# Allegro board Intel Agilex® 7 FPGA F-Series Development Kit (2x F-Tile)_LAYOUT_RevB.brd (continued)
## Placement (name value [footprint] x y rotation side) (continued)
R6892  10.0K  [0402]  31.93 15.37 180 bottom
R6893  10.0K  [0402]  32.95 15.37 180 bottom
R6894  4.70K  [0402]  39.5 40.78 180 bottom
R6895  10.0K  [0402]  32.39 25.35 270 bottom
R6896  100K  [0402]  195.71 64.47 0 bottom
R6897  1M  [0402]  74.05 98.5 0 bottom
R6898  10.0K  [0402]  72.65 42.12 90 bottom
R6899  0  [0402]  99.7 48.34 180 bottom
R6900  0  [0402]  100.72 48.34 180 bottom
R6903  243K  [0402]  220.23 66.75 90 bottom
R6904  0  [0402]  217.69 68.53 0 bottom
R6905  0, DNI  [0402]  217.69 67.64 0 bottom
R6906  0  [0402]  238.64 38.31 270 top
R6907  0  [0402]  236.48 38.31 270 top
R6908  100, DNI  [0402]  100.61 77.37 240 bottom
R6909  100, DNI  [0402]  75.95 66.53 0 bottom
R6910  100, DNI  [0402]  88.72 38.43 90 bottom
R6911  100, DNI  [0402]  75.83 47.97 180 bottom
R6912  100, DNI  [0402]  118.94 48.76 300 bottom
R6913  100, DNI  [0402]  84.6 54.25 60 bottom
R6914  100, DNI  [0402]  84.59 52.12 300 bottom
R6915  100, DNI  [0402]  84.68 59 240 bottom
R6916  100, DNI  [0402]  84.11 57.77 0 bottom
R6917  100, DNI  [0402]  117.29 70.45 60 bottom
R6918  100, DNI  [0402]  117.83 67 0 bottom
R6919  100, DNI  [0402]  84.19 61.45 0 bottom
R6920  100, DNI  [0402]  84.68 62.68 240 bottom
R6921  49.9, DNI  [0402]  74.37 51.39 270 bottom
R6922  49.9, DNI  [0402]  74.11 50.5 270 bottom
R6923  49.9, DNI  [0402]  86.89 52.58 90 bottom
R6924  49.9, DNI  [0402]  86.1 51.5 90 bottom
R6925  49.9, DNI  [0402]  75.51 59.51 90 bottom
R6926  49.9, DNI  [0402]  75.51 58.63 90 bottom
R6927  49.9, DNI  [0402]  75.51 55.58 90 bottom
R6928  49.9, DNI  [0402]  75.51 56.47 90 bottom
R6929  100, DNI  [0402]  108.55 73.65 240 bottom
R6930  DNI  [0402]  75.51 69.17 90 bottom
R6931  DNI  [0402]  75.51 70.06 90 bottom
R6932  DNI  [0402]  75.06 66.53 0 bottom
R6933  DNI  [0402]  75.51 67.86 90 bottom
R6934  DNI  [0402]  90.49 38.43 270 bottom
R6935  DNI  [0402]  86.94 38.43 90 bottom
R6936  DNI  [0402]  74.49 48.42 90 bottom
R6937  DNI  [0402]  74.49 47.53 90 bottom
R6938  DNI  [0402]  94.24 38.12 180 bottom
R6939  DNI  [0402]  95.13 38.12 180 bottom
R6940  100, DNI  [0402]  59.82 43.26 90 top
R6941  100, DNI  [0402]  63.89 43.26 90 top
R6942  100, DNI  [0402]  65.92 43.26 90 top
R6943  100, DNI  [0402]  67.95 43.26 90 top
R6944  0  [0402]  40.33 27.26 270 bottom
R6945  0  [0402]  42.23 27.26 90 bottom
S1  PB Switch  [WURTH_6X3P5_TACT_SWITCH]  211.85 103.58 90 top
S2  PB Switch  [WURTH_6X3P5_TACT_SWITCH]  216.17 103.58 90 top
S3  PB Switch  [WURTH_6X3P5_TACT_SWITCH]  220.49 103.58 90 top
S4  PB Switch  [WURTH_6X3P5_TACT_SWITCH]  224.81 103.58 90 top
S6  PB Switch  [WURTH_6X3P5_TACT_SWITCH]  229.13 103.58 90 top
ST1  -  [SHORT]  209.72 27 180 bottom
ST2  -  [SHORT]  209.19 23.3 0 bottom
ST7  -  [SHORT]  175.35 55.91 270 bottom
ST8  -  [SHORT]  164.6 42.37 90 bottom
ST9  -  [SHORT]  164.6 56.85 90 bottom
ST10  -  [SHORT]  164.6 71.33 90 bottom
ST11  -  [SHORT]  164.6 85.8 90 bottom
ST14  -  [SHORT]  164.6 27.76 90 bottom
ST20  -  [SHORT]  39.63 75.26 180 bottom
ST30  -  [SHORT]  197.49 56.42 90 bottom
ST31  -  [SHORT]  185.17 32.21 0 bottom
ST32  -  [SHORT]  22.87 64.85 0 bottom
ST33  -  [SHORT]  21.98 64.85 0 bottom
ST34  -  [SHORT]  183.52 89.36 90 bottom
SW1  TDA04H0SB1  [DIPSWITCH_SMT_QUAD]  247.66 36.53 90 top
SW2  CVS-01TB  [DIPSWITCH_SMT_SINGLE]  204.17 104.15 180 top
SW3  TDA04H0SB1  [DIPSWITCH_SMT_QUAD]  247.66 51.77 90 top
SW4  TDA04H0SB1  [DIPSWITCH_SMT_QUAD]  247.66 44.15 90 top
SW5  SW_SLIDE_DPDT  [EG2207]  245.52 98.87 0 top
SW6  CVS-01TB  [DIPSWITCH_SMT_SINGLE]  207.78 104.15 180 top
U2  24AA024-I/SN  [SOIC-8]  38.81 23.73 0 bottom
U3  MT25QU02GCBB8E12-0SIT  [T-PBGA24]  26.3 91.26 0 top
U4  MT25QU02GCBB8E12-0SIT  [T-PBGA24]  33.92 91.26 0 top
U5  10M50DAF256I7G  [MAX10_FBGA-256]  26.68 76.15 270 top
U6  TS3A5018RSVR  [UQFN-16]  26.55 95.84 0 bottom
U7  510CBA50M0000BAG  [SMT_OSC_3P2X5MM_4PIN]  13.6 71.45 0 top
U8  AGILEX_FM86  [FBGA-2340]  100.97 61.93 0 top
U9  MT25QU02GCBB8E12-0SIT  [T-PBGA24]  30.61 51.77 180 bottom
U10  510KBA125M000BAGR  [SMT_OSC_3P2X5MM_4PIN]  72.02 76.53 270 top
U12  SN74AUP1G126DCK  [SC70_TI]  56.71 105.11 90 bottom
U15  MT40A2G8VA  [FBGA-78#2]  126.16 22.56 0 top
U16  MT40A2G8VA  [FBGA-78]  113.96 22.56 0 top
U17  MT40A2G8VA  [FBGA-78]  101.77 22.56 0 top
U18  MT40A2G8VA  [FBGA-78]  89.58 22.56 0 top
U19  MT40A2G8VA  [FBGA-78#3]  77.39 22.56 0 top
U20  TPS2557DRBR  [VSON-9]  39.5 29.82 90 bottom
U21  TPS2557DRBR  [VSON-9]  30.38 43.07 90 bottom
U22  MAX3378E  [TSSOP-14]  34.55 63.2 180 bottom
U23  ZL30733LDG1Q089  [ZL30733]  63.51 49.48 180 top
U24  VCC1-9004-114M285  [SMT_OSC_7X5MM_4PIN]  55.63 59.26 180 top
U25  Si52204-A01BGM  [QFN32L]  7.88 47.96 90 bottom
U26  Si53254A-D02AM  [SI53254_QFN40]  21.98 27.13 0 bottom
U27  Si53254A-D02AM  [SI53254_QFN40]  19.82 47.96 270 bottom
U28  SN74LVC2G17DCKR  [SC70-6]  56.14 13.29 0 bottom
U31  SN74LVC2G17DCKR  [SC70-6]  49.16 13.29 0 bottom
U33  TXS0108EPWR  [20-TSSOP]  164.65 100.71 0 bottom
U36  PCA9306DC1/DG,125  [VSSOP8]  194.19 63.07 180 top
U38  PCA9306DC1/DG,125  [VSSOP8]  69.73 97.23 270 bottom
U39  PCA9306DC1/DG,125  [VSSOP8]  69.72 104.59 90 bottom
U44  M24128-BWMN6TP  [SO8]  222.87 58.68 0 top
U45  W25Q64JVSSIM  [WSOIC-8]  33.92 87.45 90 bottom
U46  M24128-BWMN6TP  [SO8]  30.26 30.15 270 bottom
U47  MAX811  [SOT-143]  9.53 98.25 180 top
U48  TPD2EUSB30  [DRT]  5.98 96.06 90 top
U49  CY7C68013A_QFN  [QFN56]  17.1 93.04 0 top
U50  MAX16545BGPF+T / MAX16550AGPN+T  [QFN-22]  226.19 43.89 270 top
U51  FDMC2514SDC  [FDMC8878_VER2]  216.67 52.15 270 bottom
U52  LTC4357  [DFN6_EPAD]  208.67 52.15 180 bottom
U53  LTC4359  [MSOP-8]  216.45 79.81 90 top
U54  MAX16545BGPF+T / MAX16550AGPN+T  [QFN-22]  228.35 80.47 90 top
U56  ISL80101  [DFN-11]  31.25 100.66 90 top
U57  ISL80101  [DFN-11]  35.57 102.19 90 bottom
U58  ISL80101  [DFN-11]  14.74 63.83 270 bottom
U60  LTC1981ES5  [LTC1981ES5_SOT23]  23.63 107.9 270 bottom
U61  LTC3888  [LTC-UHG-52-1550]  179.71 53.16 90 top
U62  LTC7051IV#PBF  [LTC-LQFN-42-1571]  156.47 40.85 0 top
U63  LTC7051IV#PBF  [LTC-LQFN-42-1571]  156.47 55.32 0 top
U64  LTC7051IV#PBF  [LTC-LQFN-42-1571]  156.47 69.8 0 top
U65  LTC7051IV#PBF  [LTC-LQFN-42-1571]  156.47 84.28 0 top
U66  LTC7051IV#PBF  [LTC-LQFN-42-1571]  156.47 26.24 0 top
U70  ISL80101  [DFN-11]  209.3 36.53 270 top
U74  ISL80101  [DFN-11]  199.52 36.53 270 top
U75  ISL80101  [DFN-11]  191.02 92.28 270 top
U76  ISL80101  [DFN-11]  144.28 19.51 0 top
U77  TPS51200DRCR  [VSON-11]  190.89 101.17 180 top
U78  TPS51200DRCR  [VSON-11]  64.65 18.11 90 top
U80  ISL80101  [DFN-11]  64.14 69.67 180 top
U81  ISL80101  [DFN-11]  64.14 61.8 180 top
U87  NLSX4014MUTAG  [UQFN12]  219.34 100.15 0 bottom
U88  NLSX4014MUTAG  [UQFN12]  211.84 100.15 0 bottom
U89  NLSX4014MUTAG  [UQFN12]  8.39 24.34 180 bottom
U90  NLSX4014MUTAG  [UQFN12]  8.39 30.56 180 bottom
U91  SN74AUP1G126DCK  [SC70_TI]  56.71 97.11 90 bottom
U93  LTC7132IY#PBF  [BGA-140#2]  50.3 86.31 0 top
U94  LTM4625IY#PBF  [BGA-25]  196.22 55.32 0 top
U95  LTM4620AIY#PBF  [BGA-144_REVERSE]  181.49 31.96 180 top
U96  LTC7132IY#PBF  [BGA-140]  194.06 77.8 270 top
U97  PCA9534PW,118  [TSSOP16]  30.36 20.65 180 bottom
X1  OCXO - ROM7050PA, DNI  [ROM7050PA]  72.91 41.99 90 top
X2  TX-801, DNI  [TX801_G320]  73.39 42.62 90 top
Y1  25.00MHz  [XTAL_FA-128]  9.28 41.23 0 bottom
Y2  24.00MHz  [XTAL_FA-128]  9.35 94.79 90 top

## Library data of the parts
B1 = Molex_QSFPDD_Cage
B2 = Molex_zQSFP_Cage_0
BT1 = Battery_0
C1 C2 C6-C15 C18 C20 C24 C26 C31-C36 C38-C47 C340-C343 C347-C350 = CAP: signal model: CAP_0201_0.22UF_0.22uF
C16 C17 C19 C21-C23 C25 C27-C30 C37 C48-C101 C107-C111 C122 C133 C135 C137 C139 C141 C143 C145 C150-C153 C157 C159 C162 C167 C169 C171 C173 C175 C177 C179 C184 C185 C187 C189 C191 C194 C195 C197-C200 C202 C203 C205-C221 C224-C246 C248 C249 C251-C267 C270-C291 C293 C295 C297-C302 C305-C307 C309 C310 C313 C314 C317 C318 C323-C325 C327 C328 C331 C332 C335 C336 C344-C346 C351-C386 C394 C395 C397-C418 C420-C424 C432-C436 C444 C449 C451 C456 C460 C461 C466 C467 C470-C473 C482 C483 C485-C494 C496-C509 C514-C517 C522-C524 C533-C541 C545 C546 C548 C549 C572-C591 C598-C606 C609 C620-C629 C651 C655 C659 C663-C665 C691 C694 C696-C698 C701 C702 C711 C719 C723 C729 C737 C738 C747 C755 C756 C765 C773 C775 C783 C791 C865 C869 C920 C925 C928 C929 C936-C938 C945 C958 C961-C963 C966-C975 C977 C981 C983 C987-C1003 C1018-C1026 C1031-C1037 C1042 C1043 C1045 C1046 C1049-C1071 C1073-C1081 C1093 C1098 C1120 C1121 C1123 C1126 C1127 C1149 C1157 C1158 C1164 C1165 C1178-C1180 C1191 C1193 C1194 C1197 C1200 C1201 C1203 C1205 C1206 C1209-C1215 C1218 C1219 C1225-C1237 C1260-C1289 = CAP: User Part Number: PART#; Tolerance: TOL
C112-C115 C525 C530 C542-C544 C550-C552 C561 C562 C571 C1047 C1048 C1072 C1224 = CAP
C116-C121 C123-C128 C144 C146 C147 C160 C178 C180 C181 C192 C201 C204 C222 C223 C247 C250 C268 C269 C292 C296 C304 C308 C311 C312 C315 C316 C319-C322 C326 C329 C330 C333 C334 C337-C339 C484 C495 C510-C513 C518-C521 C526-C529 C594-C597 C607 C608 C614 C616-C619 C648-C650 C652-C654 C656-C658 C660-C662 C688 C690 C864 C866-C868 C915 C921-C923 C926 C927 C930-C935 C939-C944 C946-C957 C959 C960 C976 C978-C980 C982 C984-C986 C1038-C1041 C1044 C1084-C1087 C1092 C1096 C1097 C1099-C1102 C1105-C1107 C1110-C1112 C1115-C1118 C1128 C1129 C1132-C1135 C1138 C1139 C1142-C1145 C1154 C1159-C1162 C1166 C1167 C1170-C1173 C1181 C1182 C1185-C1188 C1198 C1208 C1216 C1238-C1259 COUT7 COUT8 COUT13 COUT14 COUT19 COUT20 COUT31 COUT32 COUT39 = CAP: Tolerance: *; User Part Number: *
C132 C134 C136 C138 C140 C142 C154-C156 C158 C161 C166 C168 C170 C172 C174 C176 C186 C188 C190 C193 C196 C689 C1103 C1124 C1195 C1196 C1199 C1220-C1223 = Cap 10000PF 50V 0402: User Part Number: PART#; Tolerance: TOL
C148 C149 C182 C183 C703-C707 C714-C718 C720 C721 C724-C726 C732-C736 C739-C741 C743 C744 C750-C754 C757-C761 C768-C772 C776-C780 C786-C790 = CAP 10uF +/-10% 25V 1210: User Part Number: *; Tolerance: *
C303 = CAP: User Part Number: PART#; Tolerance: TOL; signal model: CAP_0402_12PF_12pF
C387-C393 C396 C1008-C1011 C1027-C1030 = CAP: User Part Number: PART#; Tolerance: TOL; signal model: CAP_0402_0.1UF_0.1uF
C450 C452 C453 C457-C459 C1125 C1202 = Cap, NP, 0402: User Part Number: PART#; Tolerance: TOL
C592 C593 C615 C1091 C1122 C1136 C1146 C1174 C1176 C1189 = PCAP
C692 C695 = CAP_P_ALT
C693 C1082 C1156 C1204 C1207 C1217 = CAP: User Part Number: 150-0578; Tolerance: TOL
C699 C700 = CAP: User Part Number: 150-3531; Tolerance: TOL
C708 C713 C722 C731 C742 C749 C762 C767 C774 C785 = CAP: User Part Number: 150-0054; Tolerance: TOL
C709 C727 C745 C763 C781 = CAP: Tolerance: *; User Part Number: 150-0576
C710 C728 C746 C764 C782 = CAP: User Part Number: 150-3126; Tolerance: TOL
C712 C730 C748 C766 C784 = CAP: Tolerance: *; User Part Number: 150-0241
COUT1-COUT6 COUT9-COUT12 COUT15-COUT18 COUT21-COUT30 COUT33-COUT37 = CAP: Tolerance: *; User Part Number: 150-3080
D1 D3-D12 D24 D25 = LED_WURTH: Tolerance: *; User Part Number: *
D2 = LED_0: Tolerance: *; User Part Number: *
D13 D15 D17 D22 D23 = TVS_5p0SMDJ12A
D14 D16 = STPS30L30DJF-TR
D18-D21 = TVS_5p0SMDJ12A: User Part Number: PART#; Tolerance: TOL
D26 D27 = TVS_2: User Part Number: *; Tolerance: *
D28 = LT1389
EU1 EU2 = MAX31730ATC
FB1 FB2 FB9-FB11 FB27-FB29 FB37-FB41 = BEAD_FERRITE_SM: User Part Number: PART#; Tolerance: TOL
FB3 = INDUCTOR: Tolerance: TOL; User Part Number: PART#
FB4-FB6 FB8 FB12-FB26 FB30 FB42 = BEAD_FERRITE_SM: Tolerance: *; User Part Number: *
FB7 = INDUCTOR
J1 = PCIE_Bracket_X16_1
J2 = FAN_Conn_0
J3 = 70247-1051
J4 J5 = DDR4x72x288_1
J6 = QSH-030-01-C-D-A
J7 = 2027180100
J8 = Molex_zQSFP_Conn
J9 = CON_MCIO_74P_G42V12312HR
J10 = MICRO_USB_CONN
J11 = 2X4_PCIE_ATX_1
J12 = 1x3_HDR_TH
J13 J107 = DF3-4P-2DSA
J14 J15 = SMA_CONN: User Part Number: XXX; Tolerance: XXX
J105 J106 = CON2
L1-L3 = INDUCTOR IRON
L5-L13 = INDUCTOR_IRON_ALT
MTH1-MTH11 = MNT HOLE_1
Q1 Q4 Q7-Q15 Q19 Q20 = PWRMOSFET_EN_GSD_0: User Part Number: *; Tolerance: *
Q2 Q3 Q21-Q24 = 2N3906_0
Q16 = PSMN1R0-30YLD_0
Q17 = PWRMOSFET_EN_GSD_1: User Part Number: *; Tolerance: *
Q18 = MOSFET N-DIODE-A-SO8_1
R1-R8 R12-R31 R40-R43 R53 R55-R59 R69 R70 R72-R78 R80 R81 R83-R102 R104 R107-R110 R114-R119 R123-R128 R134 R135 R150-R152 R163-R166 R173 R197 R206-R215 R217-R224 R227 R232-R246 R256-R272 R274 R279 R281-R287 R292-R306 R314-R326 R337-R349 R351-R353 R358 R359 R366-R370 R376-R385 R395 R398-R403 R418 R422 R425-R431 R434-R449 R451-R453 R455-R480 R494-R507 R522-R530 R532-R536 R538-R549 R556-R568 R570-R572 R574-R576 R578-R580 R582-R584 R586-R588 R590-R592 R594-R596 R598-R600 R602-R604 R606 R609 R614 R620 R637 R641-R645 R663-R668 R704 R706 R708 R709 R711-R729 R737-R750 R753-R768 R774 R777 R780 R784-R786 R789 R808 R814-R825 R833 R834 R836 R837 R839-R843 R845 R847-R849 R852 R854 R855 R857 R858 R862-R866 R868 R869 R1004 R1005 R1007 R1008 R6791 R6794 R6797-R6799 R6807-R6809 R6811-R6815 R6818 R6819 R6821 R6822 R6825 R6828-R6841 R6845-R6853 R6855 R6857-R6863 R6865 R6867-R6887 R6889 R6891-R6900 R6903-R6913 R6915-R6945 = RESISTOR: User Part Number: PART#; Tolerance: TOL
R32-R39 R52 R54 R71 R79 R103 R327 R328 R331-R334 R432 R433 R454 R770 R771 = RESISTOR: User Part Number: PART#; Tolerance: TOL; signal model: RESISTOR_0402_33.2_33.2
R82 R404-R407 R411 R6888 R6890 = RESISTOR_0: User Part Number: PART#; Tolerance: TOL
R105 R106 R139 R143 R155 R159 R167-R172 R174-R184 R186-R193 R195 R196 R200-R202 R769 R772 R773 = RESISTOR: User Part Number: PART#; Tolerance: TOL; signal model: RESISTOR_0402_10.0K_10.0K
R131 R132 R147 R148 = RESISTOR: Tolerance: *; User Part Number: *
R136-R138 R145 R153 R154 R161 R199 R307-R309 R450 R6842 R6843 = RES 0 OHM 5% 1/16W 0402 SMD: User Part Number: PART#; Tolerance: TOL
R140-R142 R156-R158 = RES 0 OHM 5% 1/16W 0402 SMD: User Part Number: PART#; Tolerance: TOL; signal model: RESISTOR_0402_10.0K_10.0K
R194 = RESISTOR: User Part Number: PART#; Tolerance: TOL; signal model: RESISTOR_0402_1.00K_1.00K
R198 = RESISTOR: User Part Number: PART#; Tolerance: TOL; signal model: RESISTOR_0402_1.00K__DNI_1.00K__DNI
R203 = RESISTOR: User Part Number: PART#; Tolerance: TOL; signal model: RESISTOR_0402_49.9__DNI_49.9__DNI
R204 R205 = RESISTOR: User Part Number: PART#; Tolerance: TOL; signal model: RESISTOR_0402_10.0K__DNI_10.0K__DNI
R225 R226 = RESISTOR: User Part Number: PART#; Tolerance: TOL; signal model: RESISTOR_0402_0_0
R228-R231 = RES_VERT_HORIZ
R247-R254 = RES 0 OHM 5% 1/16W 0402 SMD: User Part Number: PART#; Tolerance: TOL; signal model: CAP_0402_0.1UF_0.1uF
R273 R275-R278 R280 = RESISTOR: User Part Number: PART#; Tolerance: TOL; signal model: RESISTOR_0402_33_33
R288-R291 R310 R311 = RES 0 OHM 5% 1/16W 0402 SMD: User Part Number: PART#; Tolerance: TOL; signal model: RES_0_OHM_5%_1/16W_0402_SMD_0402_0_0
R312 R313 = RESISTOR: User Part Number: PART#; Tolerance: TOL; signal model: RES_0_OHM_5%_1/16W_0402_SMD_0402_0_0
R394 = Resistor, 0402: User Part Number: PART#; Tolerance: TOL
R417 = RESISTOR
R531 R569 R577 R585 R593 R601 R1006 R6802 = RES: Tolerance: *; User Part Number: 100-0163
R537 = RES: User Part Number: 100-0121; Tolerance: TOL
R550-R555 R856 R6810 R6844 = RES: User Part Number: PART#; Tolerance: TOL
R573 R581 R589 R597 R605 = RES: User Part Number: 100-2777; Tolerance: TOL
R6914 = RESISTOR: User Part Number: PART#; Tolerance: TOL; signal model: RESISTOR_0402_100__DNI_100__DNI
S1-S4 S6 = TS-A02SA-2-S100_0: User Part Number: *
ST1 ST2 = SHORT: User Part Number: *; signal model: SHORT_SHORT_SHORT_SHORT
ST7-ST11 ST14 ST20 ST30-ST34 = SHORT: User Part Number: *
SW1 SW3 SW4 = SPST4
SW2 SW6 = SPST4_0
SW5 = SW_SLIDE_DPDT: Tolerance: TOL; User Part Number: PART#
U2 = 24AA024
U3 U4 U9 = MT25QU01GBBB: Tolerance: *; User Part Number: *
U5 = 1M50DAF256I7G
U6 = TS3A5018RSVR_0
U7 U10 U24 = SiLabs_510GBA25M0000BAGR
U8 = AGILEX_FM86
U12 U91 = SN74AUP1G126DCK
U15-U19 = MT40A2G8VA
U20 U21 = TPS2557
U22 = MAX3378E_0: User Part Number: PN; Tolerance: TOL
U23 = ZL30733
U25 = Si52204
U26 U27 = Si53254A-D02AM
U28 U31 = SN74LVC2G17DCKR
U33 = MAX3002EUP+T
U36 U38 U39 = PCA9306DC,125
U44 U46 = M24128
U45 = W25Q64JVSSIM
U47 = MAX811: User Part Number: PART#; Tolerance: TOL
U48 = TPD2EUSB30: User Part Number: *; Tolerance: *
U49 = CY7C68013A_56QFN: User Part Number: *
U50 U54 = MAX16545B
U51 = FDMC8878_VER2: User Part Number: *
U52 = LTC4357: User Part Number: *
U53 = LTC4359
U56-U58 U70 U74-U76 U80 U81 = EY1501di-adj
U60 = LTC1981ES5
U61 = LTC3888-UHG
U62-U66 = LTC7501-LGA_1
U77 U78 = TPS51200_1: User Part Number: *
U87-U90 = NLSX4014MUTAG
U93 U96 = LTC7132IY#PBF
U94 = LTM4625IY#PBF
U95 = LTM4620AIY#PBF
U97 = PCA9534RGVR_1
X1 = ROM7050PA
X2 = TX-801
Y1 Y2 = CRYSTAL_SM_13: User Part Number: *

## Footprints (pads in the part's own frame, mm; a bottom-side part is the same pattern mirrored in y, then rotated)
1X3_HDR_TH
  rect 1.524x1.524 hole 1.016: 1(0,0)
  round 1.524 hole 1.016: 2(2.54,0) 3(5.08,0)
8MM_CAN
  rect 2.032x4.013 smd: 1(0,3.257) 2(0,-3.257)
16MM_BAT_HOLDER
  rect 3.607x3.454 smd: (10.303,0) 1(-10.303,0)
  rect 4.572x4.572 smd: 2(0,0)
20-TSSOP
  rect 0.406x1.778 smd: 1(-2.925,-2.946) 2(-2.275,-2.946) 3(-1.625,-2.946) 4(-0.975,-2.946) 5(-0.325,-2.946) 6(0.325,-2.946) 7(0.975,-2.946) 8(1.625,-2.946) 9(2.275,-2.946) 10(2.925,-2.946) 11(2.925,2.946) 12(2.275,2.946) 13(1.625,2.946) 14(0.975,2.946) 15(0.325,2.946) 16(-0.325,2.946) 17(-0.975,2.946) 18(-1.625,2.946) 19(-2.275,2.946) 20(-2.925,2.946)
0201
  rect 0.45x0.4 smd: 1(-0.35,0) 2(0.35,0)
0402
  rect 0.508x0.508 smd: 1(0,0.445) 2(0,-0.445)
0603
  rect 1.016x1.016 smd: 1(-0.762,0) 2(0.762,0)
0805
  rect 1.6x1.321 smd: 1(0,0.95) 2(0,-0.95)
805
  rect 1.6x1.321 smd: 1(0,0.95) 2(0,-0.95)
1206
  rect 1.27x1.778 smd: 1(-1.524,0) 2(1.524,0)
1210
  rect 1.27x2.794 smd: 1(-1.524,0) 2(1.524,0)
1210_H2P2MM
  rect 1.27x2.794 smd: 1(-1.524,0) 2(1.524,0)
2512
  rect 1.88x3.556 smd: 1(-2.737,0) 2(2.737,0)
2917
  rect 2.54x2.743 smd: 1(-3.175,0) 2(3.175,0)
2917_2MM
  rect 2.54x2.743 smd: 1(-3.175,0) 2(3.175,0)
2917_4P3MM
  rect 2.54x2.743 smd: 1(-3.175,0) 2(3.175,0)
BGA-25
  round 0.635 smd: A1(-2.54,2.54) A2(-1.27,2.54) A3(0,2.54) A4(1.27,2.54) A5(2.54,2.54) B1(-2.54,1.27) B2(-1.27,1.27) B3(0,1.27) B4(1.27,1.27) B5(2.54,1.27) C1(-2.54,0) C2(-1.27,0) C3(0,0) C4(1.27,0) C5(2.54,0) D1(-2.54,-1.27) D2(-1.27,-1.27) D3(0,-1.27) D4(1.27,-1.27) D5(2.54,-1.27) E1(-2.54,-2.54) E2(-1.27,-2.54) E3(0,-2.54) E4(1.27,-2.54) E5(2.54,-2.54)
BGA-140
  round 1.016 smd: (-8.421,-6.119) (6.643,7.135)
  round 0.406 smd: A1(-3.6,5.2) A2(-2.8,5.2) A3(-2,5.2) A4(-1.2,5.2) A5(-0.4,5.2) A6(0.4,5.2) A7(1.2,5.2) A8(2,5.2) A9(2.8,5.2) A10(3.6,5.2) B1(-3.6,4.4) B2(-2.8,4.4) B3(-2,4.4) B4(-1.2,4.4) B5(-0.4,4.4) B6(0.4,4.4) B7(1.2,4.4) B8(2,4.4) B9(2.8,4.4) B10(3.6,4.4) C1(-3.6,3.6) C2(-2.8,3.6) C3(-2,3.6) C4(-1.2,3.6) C5(-0.4,3.6) C6(0.4,3.6) C7(1.2,3.6) C8(2,3.6) C9(2.8,3.6) C10(3.6,3.6) D1(-3.6,2.8) D2(-2.8,2.8) D3(-2,2.8) D4(-1.2,2.8) D5(-0.4,2.8) D6(0.4,2.8) D7(1.2,2.8) D8(2,2.8) D9(2.8,2.8) D10(3.6,2.8) E1(-3.6,2) E2(-2.8,2) E3(-2,2) E4(-1.2,2) E5(-0.4,2) E6(0.4,2) E7(1.2,2) E8(2,2) E9(2.8,2) E10(3.6,2) F1(-3.6,1.2) F2(-2.8,1.2) F3(-2,1.2) F4(-1.2,1.2) F5(-0.4,1.2) F6(0.4,1.2) F7(1.2,1.2) F8(2,1.2) F9(2.8,1.2) F10(3.6,1.2) G1(-3.6,0.4) G2(-2.8,0.4) G3(-2,0.4) G4(-1.2,0.4) G5(-0.4,0.4) G6(0.4,0.4) G7(1.2,0.4) G8(2,0.4) G9(2.8,0.4) G10(3.6,0.4) H1(-3.6,-0.4) H2(-2.8,-0.4) H3(-2,-0.4) H4(-1.2,-0.4) H5(-0.4,-0.4) H6(0.4,-0.4) H7(1.2,-0.4) H8(2,-0.4) H9(2.8,-0.4) H10(3.6,-0.4) J1(-3.6,-1.2) J2(-2.8,-1.2) J3(-2,-1.2) J4(-1.2,-1.2) J5(-0.4,-1.2) J6(0.4,-1.2) J7(1.2,-1.2) J8(2,-1.2) J9(2.8,-1.2) J10(3.6,-1.2) K1(-3.6,-2) K2(-2.8,-2) K3(-2,-2) K4(-1.2,-2) K5(-0.4,-2) K6(0.4,-2) K7(1.2,-2) K8(2,-2) K9(2.8,-2) K10(3.6,-2) L1(-3.6,-2.8) L2(-2.8,-2.8) L3(-2,-2.8) L4(-1.2,-2.8) L5(-0.4,-2.8) L6(0.4,-2.8) L7(1.2,-2.8) L8(2,-2.8) L9(2.8,-2.8) L10(3.6,-2.8) M1(-3.6,-3.6) M2(-2.8,-3.6) M3(-2,-3.6) M4(-1.2,-3.6) M5(-0.4,-3.6) M6(0.4,-3.6) M7(1.2,-3.6) M8(2,-3.6) M9(2.8,-3.6) M10(3.6,-3.6) N1(-3.6,-4.4) N2(-2.8,-4.4) N3(-2,-4.4) N4(-1.2,-4.4) N5(-0.4,-4.4) N6(0.4,-4.4) N7(1.2,-4.4) N8(2,-4.4) N9(2.8,-4.4) N10(3.6,-4.4) P1(-3.6,-5.2) P2(-2.8,-5.2) P3(-2,-5.2) P4(-1.2,-5.2) P5(-0.4,-5.2) P6(0.4,-5.2) P7(1.2,-5.2) P8(2,-5.2) P9(2.8,-5.2) P10(3.6,-5.2)
BGA-140#2
  round 1.016 smd: (-6.897,-5.992) (6.77,5.738)
  round 0.406 smd: A1(-3.6,5.2) A2(-2.8,5.2) A3(-2,5.2) A4(-1.2,5.2) A5(-0.4,5.2) A6(0.4,5.2) A7(1.2,5.2) A8(2,5.2) A9(2.8,5.2) A10(3.6,5.2) B1(-3.6,4.4) B2(-2.8,4.4) B3(-2,4.4) B4(-1.2,4.4) B5(-0.4,4.4) B6(0.4,4.4) B7(1.2,4.4) B8(2,4.4) B9(2.8,4.4) B10(3.6,4.4) C1(-3.6,3.6) C2(-2.8,3.6) C3(-2,3.6) C4(-1.2,3.6) C5(-0.4,3.6) C6(0.4,3.6) C7(1.2,3.6) C8(2,3.6) C9(2.8,3.6) C10(3.6,3.6) D1(-3.6,2.8) D2(-2.8,2.8) D3(-2,2.8) D4(-1.2,2.8) D5(-0.4,2.8) D6(0.4,2.8) D7(1.2,2.8) D8(2,2.8) D9(2.8,2.8) D10(3.6,2.8) E1(-3.6,2) E2(-2.8,2) E3(-2,2) E4(-1.2,2) E5(-0.4,2) E6(0.4,2) E7(1.2,2) E8(2,2) E9(2.8,2) E10(3.6,2) F1(-3.6,1.2) F2(-2.8,1.2) F3(-2,1.2) F4(-1.2,1.2) F5(-0.4,1.2) F6(0.4,1.2) F7(1.2,1.2) F8(2,1.2) F9(2.8,1.2) F10(3.6,1.2) G1(-3.6,0.4) G2(-2.8,0.4) G3(-2,0.4) G4(-1.2,0.4) G5(-0.4,0.4) G6(0.4,0.4) G7(1.2,0.4) G8(2,0.4) G9(2.8,0.4) G10(3.6,0.4) H1(-3.6,-0.4) H2(-2.8,-0.4) H3(-2,-0.4) H4(-1.2,-0.4) H5(-0.4,-0.4) H6(0.4,-0.4) H7(1.2,-0.4) H8(2,-0.4) H9(2.8,-0.4) H10(3.6,-0.4) J1(-3.6,-1.2) J2(-2.8,-1.2) J3(-2,-1.2) J4(-1.2,-1.2) J5(-0.4,-1.2) J6(0.4,-1.2) J7(1.2,-1.2) J8(2,-1.2) J9(2.8,-1.2) J10(3.6,-1.2) K1(-3.6,-2) K2(-2.8,-2) K3(-2,-2) K4(-1.2,-2) K5(-0.4,-2) K6(0.4,-2) K7(1.2,-2) K8(2,-2) K9(2.8,-2) K10(3.6,-2) L1(-3.6,-2.8) L2(-2.8,-2.8) L3(-2,-2.8) L4(-1.2,-2.8) L5(-0.4,-2.8) L6(0.4,-2.8) L7(1.2,-2.8) L8(2,-2.8) L9(2.8,-2.8) L10(3.6,-2.8) M1(-3.6,-3.6) M2(-2.8,-3.6) M3(-2,-3.6) M4(-1.2,-3.6) M5(-0.4,-3.6) M6(0.4,-3.6) M7(1.2,-3.6) M8(2,-3.6) M9(2.8,-3.6) M10(3.6,-3.6) N1(-3.6,-4.4) N2(-2.8,-4.4) N3(-2,-4.4) N4(-1.2,-4.4) N5(-0.4,-4.4) N6(0.4,-4.4) N7(1.2,-4.4) N8(2,-4.4) N9(2.8,-4.4) N10(3.6,-4.4) P1(-3.6,-5.2) P2(-2.8,-5.2) P3(-2,-5.2) P4(-1.2,-5.2) P5(-0.4,-5.2) P6(0.4,-5.2) P7(1.2,-5.2) P8(2,-5.2) P9(2.8,-5.2) P10(3.6,-5.2)
BGA-144_REVERSE
  round 1.016 smd: (-11.085,14.451) (9.778,-12.307)
  round 0.635 smd: A1(-6.985,-6.985) A2(-5.715,-6.985) A3(-4.445,-6.985) A4(-3.175,-6.985) A5(-1.905,-6.985) A6(-0.635,-6.985) A7(0.635,-6.985) A8(1.905,-6.985) A9(3.175,-6.985) A10(4.445,-6.985) A11(5.715,-6.985) A12(6.985,-6.985) B1(-6.985,-5.715) B2(-5.715,-5.715) B3(-4.445,-5.715) B4(-3.175,-5.715) B5(-1.905,-5.715) B6(-0.635,-5.715) B7(0.635,-5.715) B8(1.905,-5.715) B9(3.175,-5.715) B10(4.445,-5.715) B11(5.715,-5.715) B12(6.985,-5.715) C1(-6.985,-4.445) C2(-5.715,-4.445) C3(-4.445,-4.445) C4(-3.175,-4.445) C5(-1.905,-4.445) C6(-0.635,-4.445) C7(0.635,-4.445) C8(1.905,-4.445) C9(3.175,-4.445) C10(4.445,-4.445) C11(5.715,-4.445) C12(6.985,-4.445) D1(-6.985,-3.175) D2(-5.715,-3.175) D3(-4.445,-3.175) D4(-3.175,-3.175) D5(-1.905,-3.175) D6(-0.635,-3.175) D7(0.635,-3.175) D8(1.905,-3.175) D9(3.175,-3.175) D10(4.445,-3.175) D11(5.715,-3.175) D12(6.985,-3.175) E1(-6.985,-1.905) E2(-5.715,-1.905) E3(-4.445,-1.905) E4(-3.175,-1.905) E5(-1.905,-1.905) E6(-0.635,-1.905) E7(0.635,-1.905) E8(1.905,-1.905) E9(3.175,-1.905) E10(4.445,-1.905) E11(5.715,-1.905) E12(6.985,-1.905) F1(-6.985,-0.635) F2(-5.715,-0.635) F3(-4.445,-0.635) F4(-3.175,-0.635) F5(-1.905,-0.635) F6(-0.635,-0.635) F7(0.635,-0.635) F8(1.905,-0.635) F9(3.175,-0.635) F10(4.445,-0.635) F11(5.715,-0.635) F12(6.985,-0.635) G1(-6.985,0.635) G2(-5.715,0.635) G3(-4.445,0.635) G4(-3.175,0.635) G5(-1.905,0.635) G6(-0.635,0.635) G7(0.635,0.635) G8(1.905,0.635) G9(3.175,0.635) G10(4.445,0.635) G11(5.715,0.635) G12(6.985,0.635) H1(-6.985,1.905) H2(-5.715,1.905) H3(-4.445,1.905) H4(-3.175,1.905) H5(-1.905,1.905) H6(-0.635,1.905) H7(0.635,1.905) H8(1.905,1.905) H9(3.175,1.905) H10(4.445,1.905) H11(5.715,1.905) H12(6.985,1.905) J1(-6.985,3.175) J2(-5.715,3.175) J3(-4.445,3.175) J4(-3.175,3.175) J5(-1.905,3.175) J6(-0.635,3.175) J7(0.635,3.175) J8(1.905,3.175) J9(3.175,3.175) J10(4.445,3.175) J11(5.715,3.175) J12(6.985,3.175) K1(-6.985,4.445) K2(-5.715,4.445) K3(-4.445,4.445) K4(-3.175,4.445) K5(-1.905,4.445) K6(-0.635,4.445) K7(0.635,4.445) K8(1.905,4.445) K9(3.175,4.445) K10(4.445,4.445) K11(5.715,4.445) K12(6.985,4.445) L1(-6.985,5.715) L2(-5.715,5.715) L3(-4.445,5.715) L4(-3.175,5.715) L5(-1.905,5.715) L6(-0.635,5.715) L7(0.635,5.715) L8(1.905,5.715) L9(3.175,5.715) L10(4.445,5.715) L11(5.715,5.715) L12(6.985,5.715) M1(-6.985,6.985) M2(-5.715,6.985) M3(-4.445,6.985) M4(-3.175,6.985) M5(-1.905,6.985) M6(-0.635,6.985) M7(0.635,6.985) M8(1.905,6.985) M9(3.175,6.985) M10(4.445,6.985) M11(5.715,6.985) M12(6.985,6.985)
DDR4DIMM_SMT
  round 3.226 hole 2.464: (-68.975,0) (68.975,0)
  oval 1.727x2.972 hole 1.219x2.464: (5.575,0)
  rect 0.584x1.803 smd: 1(-63.325,-2.3) 2(-62.475,-2.3) 3(-61.625,-2.3) 4(-60.775,-2.3) 5(-59.925,-2.3) 6(-59.075,-2.3) 7(-58.225,-2.3) 8(-57.375,-2.3) 9(-56.525,-2.3) 10(-55.675,-2.3) 11(-54.825,-2.3) 12(-53.975,-2.3) 13(-53.125,-2.3) 14(-52.275,-2.3) 15(-51.425,-2.3) 16(-50.575,-2.3) 17(-49.725,-2.3) 18(-48.875,-2.3) 19(-48.025,-2.3) 20(-47.175,-2.3) 21(-46.325,-2.3) 22(-45.475,-2.3) 23(-44.625,-2.3) 24(-43.775,-2.3) 25(-42.925,-2.3) 26(-42.075,-2.3) 27(-41.225,-2.3) 28(-40.375,-2.3) 29(-39.525,-2.3) 30(-38.675,-2.3) 31(-37.825,-2.3) 32(-36.975,-2.3) 33(-36.125,-2.3) 34(-35.275,-2.3) 35(-34.425,-2.3) 36(-33.575,-2.3) 37(-32.725,-2.3) 38(-31.875,-2.3) 39(-31.025,-2.3) 40(-30.175,-2.3) 41(-29.325,-2.3) 42(-28.475,-2.3) 43(-27.625,-2.3) 44(-26.775,-2.3) 45(-25.925,-2.3) 46(-25.075,-2.3) 47(-24.225,-2.3) 48(-23.375,-2.3) 49(-22.525,-2.3) 50(-21.675,-2.3) 51(-20.825,-2.3) 52(-19.975,-2.3) 53(-19.125,-2.3) 54(-18.275,-2.3) 55(-17.425,-2.3) 56(-16.575,-2.3) 57(-15.725,-2.3) 58(-14.875,-2.3) 59(-14.025,-2.3) 60(-13.175,-2.3) 61(-12.325,-2.3) 62(-11.475,-2.3) 63(-10.625,-2.3) 64(-9.775,-2.3) 65(-8.925,-2.3) 66(-8.075,-2.3) 67(-7.225,-2.3) 68(-6.375,-2.3) 69(-5.525,-2.3) 70(-4.675,-2.3) 71(-3.825,-2.3) 72(-2.975,-2.3) 73(-2.125,-2.3) 74(-1.275,-2.3) 75(-0.425,-2.3) 76(0.425,-2.3) 77(1.275,-2.3) 78(7.225,-2.3) 79(8.075,-2.3) 80(8.925,-2.3) 81(9.775,-2.3) 82(10.625,-2.3) 83(11.475,-2.3) 84(12.325,-2.3) 85(13.175,-2.3) 86(14.025,-2.3) 87(14.875,-2.3) 88(15.725,-2.3) 89(16.575,-2.3) 90(17.425,-2.3) 91(18.275,-2.3) 92(19.125,-2.3) 93(19.975,-2.3) 94(20.825,-2.3) 95(21.675,-2.3) 96(22.525,-2.3) 97(23.375,-2.3) 98(24.225,-2.3) 99(25.075,-2.3) 100(25.925,-2.3) 101(26.775,-2.3) 102(27.625,-2.3) 103(28.475,-2.3) 104(29.325,-2.3) 105(30.175,-2.3) 106(31.025,-2.3) 107(31.875,-2.3) 108(32.725,-2.3) 109(33.575,-2.3) 110(34.425,-2.3) 111(35.275,-2.3) 112(36.125,-2.3) 113(36.975,-2.3) 114(37.825,-2.3) 115(38.675,-2.3) 116(39.525,-2.3) 117(40.375,-2.3) 118(41.225,-2.3) 119(42.075,-2.3) 120(42.925,-2.3) 121(43.775,-2.3) 122(44.625,-2.3) 123(45.475,-2.3) 124(46.325,-2.3) 125(47.175,-2.3) 126(48.025,-2.3) 127(48.875,-2.3) 128(49.725,-2.3) 129(50.575,-2.3) 130(51.425,-2.3) 131(52.275,-2.3) 132(53.125,-2.3) 133(53.975,-2.3) 134(54.825,-2.3) 135(55.675,-2.3) 136(56.525,-2.3) 137(57.375,-2.3) 138(58.225,-2.3) 139(59.075,-2.3) 140(59.925,-2.3) 141(60.775,-2.3) 142(61.625,-2.3) 143(62.475,-2.3) 144(63.325,-2.3) 145(-63.325,2.3) 146(-62.475,2.3) 147(-61.625,2.3) 148(-60.775,2.3) 149(-59.925,2.3) 150(-59.075,2.3) 151(-58.225,2.3) 152(-57.375,2.3) 153(-56.525,2.3) 154(-55.675,2.3) 155(-54.825,2.3) 156(-53.975,2.3) 157(-53.125,2.3) 158(-52.275,2.3) 159(-51.425,2.3) 160(-50.575,2.3) 161(-49.725,2.3) 162(-48.875,2.3) 163(-48.025,2.3) 164(-47.175,2.3) 165(-46.325,2.3) 166(-45.475,2.3) 167(-44.625,2.3) 168(-43.775,2.3) 169(-42.925,2.3) 170(-42.075,2.3) 171(-41.225,2.3) 172(-40.375,2.3) 173(-39.525,2.3) 174(-38.675,2.3) 175(-37.825,2.3) 176(-36.975,2.3) 177(-36.125,2.3) 178(-35.275,2.3) 179(-34.425,2.3) 180(-33.575,2.3) 181(-32.725,2.3) 182(-31.875,2.3) 183(-31.025,2.3) 184(-30.175,2.3) 185(-29.325,2.3) 186(-28.475,2.3) 187(-27.625,2.3) 188(-26.775,2.3) 189(-25.925,2.3) 190(-25.075,2.3) 191(-24.225,2.3) 192(-23.375,2.3) 193(-22.525,2.3) 194(-21.675,2.3) 195(-20.825,2.3) 196(-19.975,2.3) 197(-19.125,2.3) 198(-18.275,2.3) 199(-17.425,2.3) 200(-16.575,2.3) 201(-15.725,2.3) 202(-14.875,2.3) 203(-14.025,2.3) 204(-13.175,2.3) 205(-12.325,2.3) 206(-11.475,2.3) 207(-10.625,2.3) 208(-9.775,2.3) 209(-8.925,2.3) 210(-8.075,2.3) 211(-7.225,2.3) 212(-6.375,2.3) 213(-5.525,2.3) 214(-4.675,2.3) 215(-3.825,2.3) 216(-2.975,2.3) 217(-2.125,2.3) 218(-1.275,2.3) 219(-0.425,2.3) 220(0.425,2.3) 221(1.275,2.3) 222(7.225,2.3) 223(8.075,2.3) 224(8.925,2.3) 225(9.775,2.3) 226(10.625,2.3) 227(11.475,2.3) 228(12.325,2.3) 229(13.175,2.3) 230(14.025,2.3) 231(14.875,2.3) 232(15.725,2.3) 233(16.575,2.3) 234(17.425,2.3) 235(18.275,2.3) 236(19.125,2.3) 237(19.975,2.3) 238(20.825,2.3) 239(21.675,2.3) 240(22.525,2.3) 241(23.375,2.3) 242(24.225,2.3) 243(25.075,2.3) 244(25.925,2.3) 245(26.775,2.3) 246(27.625,2.3) 247(28.475,2.3) 248(29.325,2.3) 249(30.175,2.3) 250(31.025,2.3) 251(31.875,2.3) 252(32.725,2.3) 253(33.575,2.3) 254(34.425,2.3) 255(35.275,2.3) 256(36.125,2.3) 257(36.975,2.3) 258(37.825,2.3) 259(38.675,2.3) 260(39.525,2.3) 261(40.375,2.3) 262(41.225,2.3) 263(42.075,2.3) 264(42.925,2.3) 265(43.775,2.3) 266(44.625,2.3) 267(45.475,2.3) 268(46.325,2.3) 269(47.175,2.3) 270(48.025,2.3) 271(48.875,2.3) 272(49.725,2.3) 273(50.575,2.3) 274(51.425,2.3) 275(52.275,2.3) 276(53.125,2.3) 277(53.975,2.3) 278(54.825,2.3) 279(55.675,2.3) 280(56.525,2.3) 281(57.375,2.3) 282(58.225,2.3) 283(59.075,2.3) 284(59.925,2.3) 285(60.775,2.3) 286(61.625,2.3) 287(62.475,2.3) 288(63.325,2.3)
DF3-4P-2DSA_01
  rect 1.422x1.422 hole 0.914: 1(0,0)
  round 1.422 hole 0.914: 2(0,2) 3(0,4) 4(0,6)
DFN6_EPAD
  rect 0.25x0.7 smd: 1(-0.5,-1.425) 2(0,-1.425) 3(0.5,-1.425) 4(0.5,1.425) 5(0,1.425) 6(-0.5,1.425)
  rect 1.321x1.6 smd: 7(0,0)
DFN-11
  rect 0.483x0.737 smd: 1(-1.102,-1.518) 5(1.102,-1.518) 6(1.102,1.518) 10(-1.102,1.518)
  rect 0.279x0.737 smd: 2(-0.5,-1.518) 3(0,-1.518) 4(0.5,-1.518) 7(0.5,1.518) 8(0,1.518) 9(-0.5,1.518)
  rect 2.007x1.6 smd: 11(0,0)
DIPSWITCH_SMT_QUAD
  rect 0.76x1.27 smd: 1(-1.905,-3.81) 2(-0.635,-3.81) 3(0.635,-3.81) 4(1.905,-3.81) 5(1.905,3.81) 6(0.635,3.81) 7(-0.635,3.81) 8(-1.905,3.81)
DIPSWITCH_SMT_SINGLE
  rect 0.711x0.711 smd: (-1.056,2.156) (-1.056,-2.156) (1.056,2.156) (1.056,-2.156)
  rect 0.711x1.219 smd: 1(0,2.96) 2(0,-2.96)
DRT
  rect 0.305x0.305 smd: 1(-0.35,-0.425) 2(0.35,-0.425) 3(0,0.425)
EATON_FP0805R1-R07-R
  rect 3.556x3.175 smd: 1(0,2.738) 2(0,-2.738)
EG2207
  round 1.778 hole 1.194: (-2.794,-1.003) (6.807,-1.003)
  rect 1.346x1.346 hole 0.787: 1(0,0)
  round 1.346 hole 0.787: 2(2.007,0) 3(4.013,0) 4(0,-2.007) 5(2.007,-2.007) 6(4.013,-2.007)
FBGA-78
  round 1.016 smd: (-6,-6.4) (6,6.476)
  round 0.42 smd: A1(-3.2,4.8) A2(-2.4,4.8) A3(-1.6,4.8) A7(1.6,4.8) A8(2.4,4.8) A9(3.2,4.8) B1(-3.2,4) B2(-2.4,4) B3(-1.6,4) B7(1.6,4) B8(2.4,4) B9(3.2,4) C1(-3.2,3.2) C2(-2.4,3.2) C3(-1.6,3.2) C7(1.6,3.2) C8(2.4,3.2) C9(3.2,3.2) D1(-3.2,2.4) D2(-2.4,2.4) D3(-1.6,2.4) D7(1.6,2.4) D8(2.4,2.4) D9(3.2,2.4) E1(-3.2,1.6) E2(-2.4,1.6) E3(-1.6,1.6) E7(1.6,1.6) E8(2.4,1.6) E9(3.2,1.6) F1(-3.2,0.8) F2(-2.4,0.8) F3(-1.6,0.8) F7(1.6,0.8) F8(2.4,0.8) F9(3.2,0.8) G1(-3.2,0) G2(-2.4,0) G3(-1.6,0) G7(1.6,0) G8(2.4,0) G9(3.2,0) H1(-3.2,-0.8) H2(-2.4,-0.8) H3(-1.6,-0.8) H7(1.6,-0.8) H8(2.4,-0.8) H9(3.2,-0.8) J1(-3.2,-1.6) J2(-2.4,-1.6) J3(-1.6,-1.6) J7(1.6,-1.6) J8(2.4,-1.6) J9(3.2,-1.6) K1(-3.2,-2.4) K2(-2.4,-2.4) K3(-1.6,-2.4) K7(1.6,-2.4) K8(2.4,-2.4) K9(3.2,-2.4) L1(-3.2,-3.2) L2(-2.4,-3.2) L3(-1.6,-3.2) L7(1.6,-3.2) L8(2.4,-3.2) L9(3.2,-3.2) M1(-3.2,-4) M2(-2.4,-4) M3(-1.6,-4) M7(1.6,-4) M8(2.4,-4) M9(3.2,-4) N1(-3.2,-4.8) N2(-2.4,-4.8) N3(-1.6,-4.8) N7(1.6,-4.8) N8(2.4,-4.8) N9(3.2,-4.8)
FBGA-78#2
  round 1.016 smd: (-6,-6.4) (6,6.4)
  round 0.42 smd: A1(-3.2,4.8) A2(-2.4,4.8) A3(-1.6,4.8) A7(1.6,4.8) A8(2.4,4.8) A9(3.2,4.8) B1(-3.2,4) B2(-2.4,4) B3(-1.6,4) B7(1.6,4) B8(2.4,4) B9(3.2,4) C1(-3.2,3.2) C2(-2.4,3.2) C3(-1.6,3.2) C7(1.6,3.2) C8(2.4,3.2) C9(3.2,3.2) D1(-3.2,2.4) D2(-2.4,2.4) D3(-1.6,2.4) D7(1.6,2.4) D8(2.4,2.4) D9(3.2,2.4) E1(-3.2,1.6) E2(-2.4,1.6) E3(-1.6,1.6) E7(1.6,1.6) E8(2.4,1.6) E9(3.2,1.6) F1(-3.2,0.8) F2(-2.4,0.8) F3(-1.6,0.8) F7(1.6,0.8) F8(2.4,0.8) F9(3.2,0.8) G1(-3.2,0) G2(-2.4,0) G3(-1.6,0) G7(1.6,0) G8(2.4,0) G9(3.2,0) H1(-3.2,-0.8) H2(-2.4,-0.8) H3(-1.6,-0.8) H7(1.6,-0.8) H8(2.4,-0.8) H9(3.2,-0.8) J1(-3.2,-1.6) J2(-2.4,-1.6) J3(-1.6,-1.6) J7(1.6,-1.6) J8(2.4,-1.6) J9(3.2,-1.6) K1(-3.2,-2.4) K2(-2.4,-2.4) K3(-1.6,-2.4) K7(1.6,-2.4) K8(2.4,-2.4) K9(3.2,-2.4) L1(-3.2,-3.2) L2(-2.4,-3.2) L3(-1.6,-3.2) L7(1.6,-3.2) L8(2.4,-3.2) L9(3.2,-3.2) M1(-3.2,-4) M2(-2.4,-4) M3(-1.6,-4) M7(1.6,-4) M8(2.4,-4) M9(3.2,-4) N1(-3.2,-4.8) N2(-2.4,-4.8) N3(-1.6,-4.8) N7(1.6,-4.8) N8(2.4,-4.8) N9(3.2,-4.8)
FBGA-78#3
  round 1.016 smd: (-5.111,-7.162) (6,6.476)
  round 0.42 smd: A1(-3.2,4.8) A2(-2.4,4.8) A3(-1.6,4.8) A7(1.6,4.8) A8(2.4,4.8) A9(3.2,4.8) B1(-3.2,4) B2(-2.4,4) B3(-1.6,4) B7(1.6,4) B8(2.4,4) B9(3.2,4) C1(-3.2,3.2) C2(-2.4,3.2) C3(-1.6,3.2) C7(1.6,3.2) C8(2.4,3.2) C9(3.2,3.2) D1(-3.2,2.4) D2(-2.4,2.4) D3(-1.6,2.4) D7(1.6,2.4) D8(2.4,2.4) D9(3.2,2.4) E1(-3.2,1.6) E2(-2.4,1.6) E3(-1.6,1.6) E7(1.6,1.6) E8(2.4,1.6) E9(3.2,1.6) F1(-3.2,0.8) F2(-2.4,0.8) F3(-1.6,0.8) F7(1.6,0.8) F8(2.4,0.8) F9(3.2,0.8) G1(-3.2,0) G2(-2.4,0) G3(-1.6,0) G7(1.6,0) G8(2.4,0) G9(3.2,0) H1(-3.2,-0.8) H2(-2.4,-0.8) H3(-1.6,-0.8) H7(1.6,-0.8) H8(2.4,-0.8) H9(3.2,-0.8) J1(-3.2,-1.6) J2(-2.4,-1.6) J3(-1.6,-1.6) J7(1.6,-1.6) J8(2.4,-1.6) J9(3.2,-1.6) K1(-3.2,-2.4) K2(-2.4,-2.4) K3(-1.6,-2.4) K7(1.6,-2.4) K8(2.4,-2.4) K9(3.2,-2.4) L1(-3.2,-3.2) L2(-2.4,-3.2) L3(-1.6,-3.2) L7(1.6,-3.2) L8(2.4,-3.2) L9(3.2,-3.2) M1(-3.2,-4) M2(-2.4,-4) M3(-1.6,-4) M7(1.6,-4) M8(2.4,-4) M9(3.2,-4) N1(-3.2,-4.8) N2(-2.4,-4.8) N3(-1.6,-4.8) N7(1.6,-4.8) N8(2.4,-4.8) N9(3.2,-4.8)
FBGA-2340
  round 1.016 smd: (-23.5,-22) (23.5,22)
  round 0.5 smd: A3(19.919,-20.24) A53(-19.919,-20.24) B2(20.715,-19.78) B54(-20.715,-19.78) C1(21.512,-19.32) C55(-21.512,-19.32) DG1(21.512,19.32) DG55(-21.512,19.32) DH2(20.715,19.78) DH54(-20.715,19.78) DJ3(19.919,20.24) DJ53(-19.919,20.24)
  round 0.475 smd: A5(18.325,-20.24) A51(-18.325,-20.24) B4(19.122,-19.78) B52(-19.122,-19.78) C3(19.919,-19.32) C53(-19.919,-19.32) D2(20.715,-18.86) D54(-20.715,-18.86) DE1(21.512,18.4) DE55(-21.512,18.4) DF2(20.715,18.86) DF54(-20.715,18.86) DG3(19.919,19.32) DG53(-19.919,19.32) DH4(19.122,19.78) DH52(-19.122,19.78) DJ5(18.325,20.24) DJ51(-18.325,20.24) E1(21.512,-18.4) E55(-21.512,-18.4)
  round 0.45 smd: A7(16.732,-20.24) A9(15.138,-20.24) A11(13.545,-20.24) A13(11.951,-20.24) A15(10.358,-20.24) A17(8.764,-20.24) A19(7.171,-20.24) A21(5.577,-20.24) A23(3.984,-20.24) A25(2.39,-20.24) A27(0.797,-20.24) A29(-0.797,-20.24) A31(-2.39,-20.24) A33(-3.984,-20.24) A35(-5.577,-20.24) A37(-7.171,-20.24) A39(-8.764,-20.24) A41(-10.358,-20.24) A43(-11.951,-20.24) A45(-13.545,-20.24) A47(-15.138,-20.24) A49(-16.732,-20.24) AA1(21.512,-11.04) AA3(19.919,-11.04) AA5(18.325,-11.04) AA7(16.732,-11.04) AA9(15.138,-11.04) AA11(13.545,-11.04) AA13(11.951,-11.04) AA15(10.358,-11.04) AA17(8.764,-11.04) AA19(7.171,-11.04) AA21(5.577,-11.04) AA23(3.984,-11.04) AA25(2.39,-11.04) AA27(0.797,-11.04) AA29(-0.797,-11.04) AA31(-2.39,-11.04) AA33(-3.984,-11.04) AA35(-5.577,-11.04) AA37(-7.171,-11.04) AA39(-8.764,-11.04) AA41(-10.358,-11.04) AA43(-11.951,-11.04) AA45(-13.545,-11.04) AA47(-15.138,-11.04) AA49(-16.732,-11.04) AA51(-18.325,-11.04) AA53(-19.919,-11.04) AA55(-21.512,-11.04) AB2(20.715,-10.58) AB4(19.122,-10.58) AB6(17.528,-10.58) AB8(15.935,-10.58) AB10(14.341,-10.58) AB12(12.748,-10.58) AB14(11.154,-10.58) AB16(9.561,-10.58) AB18(7.967,-10.58) AB20(6.374,-10.58) AB22(4.78,-10.58) AB24(3.187,-10.58) AB26(1.593,-10.58) AB28(0,-10.58) AB30(-1.593,-10.58) AB32(-3.187,-10.58) AB34(-4.78,-10.58) AB36(-6.374,-10.58) AB38(-7.967,-10.58) AB40(-9.561,-10.58) AB42(-11.154,-10.58) AB44(-12.748,-10.58) AB46(-14.341,-10.58) AB48(-15.935,-10.58) AB50(-17.528,-10.58) AB52(-19.122,-10.58) AB54(-20.715,-10.58) AC1(21.512,-10.12) AC3(19.919,-10.12) AC5(18.325,-10.12) AC7(16.732,-10.12) AC9(15.138,-10.12) AC11(13.545,-10.12) AC13(11.951,-10.12) AC15(10.358,-10.12) AC17(8.764,-10.12) AC19(7.171,-10.12) AC21(5.577,-10.12) AC23(3.984,-10.12) AC25(2.39,-10.12) AC27(0.797,-10.12) AC29(-0.797,-10.12) AC31(-2.39,-10.12) AC33(-3.984,-10.12) AC35(-5.577,-10.12) AC37(-7.171,-10.12) AC39(-8.764,-10.12) AC41(-10.358,-10.12) AC43(-11.951,-10.12) AC45(-13.545,-10.12) AC47(-15.138,-10.12) AC49(-16.732,-10.12) AC51(-18.325,-10.12) AC53(-19.919,-10.12) AC55(-21.512,-10.12) AD2(20.715,-9.66) AD4(19.122,-9.66) AD6(17.528,-9.66) AD8(15.935,-9.66) AD10(14.341,-9.66) AD12(12.748,-9.66) AD14(11.154,-9.66) AD16(9.561,-9.66) AD18(7.967,-9.66) AD20(6.374,-9.66) AD22(4.78,-9.66) AD24(3.187,-9.66) AD26(1.593,-9.66) AD28(0,-9.66) AD30(-1.593,-9.66) AD32(-3.187,-9.66) AD34(-4.78,-9.66) AD36(-6.374,-9.66) AD38(-7.967,-9.66) AD40(-9.561,-9.66) AD42(-11.154,-9.66) AD44(-12.748,-9.66) AD46(-14.341,-9.66) AD48(-15.935,-9.66) AD50(-17.528,-9.66) AD52(-19.122,-9.66) AD54(-20.715,-9.66) AE1(21.512,-9.2) AE3(19.919,-9.2) AE5(18.325,-9.2) AE7(16.732,-9.2) AE9(15.138,-9.2) AE11(13.545,-9.2) AE13(11.951,-9.2) AE15(10.358,-9.2) AE17(8.764,-9.2) AE19(7.171,-9.2) AE21(5.577,-9.2) AE23(3.984,-9.2) AE25(2.39,-9.2) AE27(0.797,-9.2) AE29(-0.797,-9.2) AE31(-2.39,-9.2) AE33(-3.984,-9.2) AE35(-5.577,-9.2) AE37(-7.171,-9.2) AE39(-8.764,-9.2) AE41(-10.358,-9.2) AE43(-11.951,-9.2) AE45(-13.545,-9.2) AE47(-15.138,-9.2) AE49(-16.732,-9.2) AE51(-18.325,-9.2) AE53(-19.919,-9.2) AE55(-21.512,-9.2) AF2(20.715,-8.74) AF4(19.122,-8.74) AF6(17.528,-8.74) AF8(15.935,-8.74) AF10(14.341,-8.74) AF12(12.748,-8.74) AF14(11.154,-8.74) AF16(9.561,-8.74) AF18(7.967,-8.74) AF20(6.374,-8.74) AF22(4.78,-8.74) AF24(3.187,-8.74) AF26(1.593,-8.74) AF28(0,-8.74) AF30(-1.593,-8.74) AF32(-3.187,-8.74) AF34(-4.78,-8.74) AF36(-6.374,-8.74) AF38(-7.967,-8.74) AF40(-9.561,-8.74) AF42(-11.154,-8.74) AF44(-12.748,-8.74) AF46(-14.341,-8.74) AF48(-15.935,-8.74) AF50(-17.528,-8.74) AF52(-19.122,-8.74) AF54(-20.715,-8.74) AG1(21.512,-8.28) AG3(19.919,-8.28) AG5(18.325,-8.28) AG7(16.732,-8.28) AG9(15.138,-8.28) AG11(13.545,-8.28) AG13(11.951,-8.28) AG15(10.358,-8.28) AG17(8.764,-8.28) AG19(7.171,-8.28) AG21(5.577,-8.28) AG23(3.984,-8.28) AG25(2.39,-8.28) AG27(0.797,-8.28) AG29(-0.797,-8.28) AG31(-2.39,-8.28) AG33(-3.984,-8.28) AG35(-5.577,-8.28) AG37(-7.171,-8.28) AG39(-8.764,-8.28) AG41(-10.358,-8.28) AG43(-11.951,-8.28) AG45(-13.545,-8.28) AG47(-15.138,-8.28) AG49(-16.732,-8.28) AG51(-18.325,-8.28) AG53(-19.919,-8.28) AG55(-21.512,-8.28) AH2(20.715,-7.82) AH4(19.122,-7.82) AH6(17.528,-7.82) AH8(15.935,-7.82) AH10(14.341,-7.82) AH12(12.748,-7.82) AH14(11.154,-7.82) AH16(9.561,-7.82) AH18(7.967,-7.82) AH20(6.374,-7.82) AH22(4.78,-7.82) AH24(3.187,-7.82) AH26(1.593,-7.82) AH28(0,-7.82) AH30(-1.593,-7.82) AH32(-3.187,-7.82) AH34(-4.78,-7.82) AH36(-6.374,-7.82) AH38(-7.967,-7.82) AH40(-9.561,-7.82) AH42(-11.154,-7.82) AH44(-12.748,-7.82) AH46(-14.341,-7.82) AH48(-15.935,-7.82) AH50(-17.528,-7.82) AH52(-19.122,-7.82) AH54(-20.715,-7.82) AJ1(21.512,-7.36) AJ3(19.919,-7.36) AJ5(18.325,-7.36) AJ7(16.732,-7.36) AJ9(15.138,-7.36) AJ11(13.545,-7.36) AJ13(11.951,-7.36) AJ15(10.358,-7.36) AJ17(8.764,-7.36) AJ19(7.171,-7.36) AJ21(5.577,-7.36) AJ23(3.984,-7.36) AJ25(2.39,-7.36) AJ27(0.797,-7.36) AJ29(-0.797,-7.36) AJ31(-2.39,-7.36) AJ33(-3.984,-7.36) AJ35(-5.577,-7.36) AJ37(-7.171,-7.36) AJ39(-8.764,-7.36) AJ41(-10.358,-7.36) AJ43(-11.951,-7.36) AJ45(-13.545,-7.36) AJ47(-15.138,-7.36) AJ49(-16.732,-7.36) AJ51(-18.325,-7.36) AJ53(-19.919,-7.36) AJ55(-21.512,-7.36) AK2(20.715,-6.9) AK4(19.122,-6.9) AK6(17.528,-6.9) AK8(15.935,-6.9) AK10(14.341,-6.9) AK12(12.748,-6.9) AK14(11.154,-6.9) AK16(9.561,-6.9) AK18(7.967,-6.9) AK20(6.374,-6.9) AK22(4.78,-6.9) AK24(3.187,-6.9) AK26(1.593,-6.9) AK28(0,-6.9) AK30(-1.593,-6.9) AK32(-3.187,-6.9) AK34(-4.78,-6.9) AK36(-6.374,-6.9) AK38(-7.967,-6.9) AK40(-9.561,-6.9) AK42(-11.154,-6.9) AK44(-12.748,-6.9) AK46(-14.341,-6.9) AK48(-15.935,-6.9) AK50(-17.528,-6.9) AK52(-19.122,-6.9) AK54(-20.715,-6.9) AL1(21.512,-6.44) AL3(19.919,-6.44) AL5(18.325,-6.44) AL7(16.732,-6.44) AL9(15.138,-6.44) AL11(13.545,-6.44) AL13(11.951,-6.44) AL15(10.358,-6.44) AL17(8.764,-6.44) AL19(7.171,-6.44) AL21(5.577,-6.44) AL23(3.984,-6.44) AL25(2.39,-6.44) AL27(0.797,-6.44) AL29(-0.797,-6.44) AL31(-2.39,-6.44) AL33(-3.984,-6.44) AL35(-5.577,-6.44) AL37(-7.171,-6.44) AL39(-8.764,-6.44) AL41(-10.358,-6.44) AL43(-11.951,-6.44) AL45(-13.545,-6.44) AL47(-15.138,-6.44) AL49(-16.732,-6.44) AL51(-18.325,-6.44) AL53(-19.919,-6.44) AL55(-21.512,-6.44) AM2(20.715,-5.98) AM4(19.122,-5.98) AM6(17.528,-5.98) AM8(15.935,-5.98) AM10(14.341,-5.98) AM12(12.748,-5.98) AM14(11.154,-5.98) AM16(9.561,-5.98) AM18(7.967,-5.98) AM20(6.374,-5.98) AM22(4.78,-5.98) AM24(3.187,-5.98) AM26(1.593,-5.98) AM28(0,-5.98) AM30(-1.593,-5.98) AM32(-3.187,-5.98) AM34(-4.78,-5.98) AM36(-6.374,-5.98) AM38(-7.967,-5.98) AM40(-9.561,-5.98) AM42(-11.154,-5.98) AM44(-12.748,-5.98) AM46(-14.341,-5.98) AM48(-15.935,-5.98) AM50(-17.528,-5.98) AM52(-19.122,-5.98) AM54(-20.715,-5.98) AN1(21.512,-5.52) AN3(19.919,-5.52) AN5(18.325,-5.52) AN7(16.732,-5.52) AN9(15.138,-5.52) AN11(13.545,-5.52) AN13(11.951,-5.52) AN15(10.358,-5.52) AN17(8.764,-5.52) AN19(7.171,-5.52) AN21(5.577,-5.52) AN23(3.984,-5.52) AN25(2.39,-5.52) AN27(0.797,-5.52) AN29(-0.797,-5.52) AN31(-2.39,-5.52) AN33(-3.984,-5.52) AN35(-5.577,-5.52) AN37(-7.171,-5.52) AN39(-8.764,-5.52) AN41(-10.358,-5.52) AN43(-11.951,-5.52) AN45(-13.545,-5.52) AN47(-15.138,-5.52) AN49(-16.732,-5.52) AN51(-18.325,-5.52) AN53(-19.919,-5.52) AN55(-21.512,-5.52) AP2(20.715,-5.06) AP4(19.122,-5.06) AP6(17.528,-5.06) AP8(15.935,-5.06) AP10(14.341,-5.06) AP12(12.748,-5.06) AP14(11.154,-5.06) AP16(9.561,-5.06) AP18(7.967,-5.06) AP20(6.374,-5.06) AP22(4.78,-5.06) AP24(3.187,-5.06) AP26(1.593,-5.06) AP28(0,-5.06) AP30(-1.593,-5.06) AP32(-3.187,-5.06) AP34(-4.78,-5.06) AP36(-6.374,-5.06) AP38(-7.967,-5.06) AP40(-9.561,-5.06) AP42(-11.154,-5.06) AP44(-12.748,-5.06) AP46(-14.341,-5.06) AP48(-15.935,-5.06) AP50(-17.528,-5.06) AP52(-19.122,-5.06) AP54(-20.715,-5.06) AR1(21.512,-4.6) AR3(19.919,-4.6) AR5(18.325,-4.6) AR7(16.732,-4.6) AR9(15.138,-4.6) AR11(13.545,-4.6) AR13(11.951,-4.6) AR15(10.358,-4.6) AR17(8.764,-4.6) AR19(7.171,-4.6) AR21(5.577,-4.6) AR23(3.984,-4.6) AR25(2.39,-4.6) AR27(0.797,-4.6) AR29(-0.797,-4.6) AR31(-2.39,-4.6) AR33(-3.984,-4.6) AR35(-5.577,-4.6) AR37(-7.171,-4.6) AR39(-8.764,-4.6) AR41(-10.358,-4.6) AR43(-11.951,-4.6) AR45(-13.545,-4.6) AR47(-15.138,-4.6) AR49(-16.732,-4.6) AR51(-18.325,-4.6) AR53(-19.919,-4.6) AR55(-21.512,-4.6) AT2(20.715,-4.14) AT4(19.122,-4.14) AT6(17.528,-4.14) AT8(15.935,-4.14) AT10(14.341,-4.14) AT12(12.748,-4.14) AT14(11.154,-4.14) AT16(9.561,-4.14) AT18(7.967,-4.14) AT20(6.374,-4.14) AT22(4.78,-4.14) AT34(-4.78,-4.14) AT36(-6.374,-4.14) AT38(-7.967,-4.14) AT40(-9.561,-4.14) AT42(-11.154,-4.14) AT44(-12.748,-4.14) AT46(-14.341,-4.14) AT48(-15.935,-4.14) AT50(-17.528,-4.14) AT52(-19.122,-4.14) AT54(-20.715,-4.14) AU1(21.512,-3.68) AU3(19.919,-3.68) AU5(18.325,-3.68) AU7(16.732,-3.68) AU9(15.138,-3.68) AU11(13.545,-3.68) AU13(11.951,-3.68) AU15(10.358,-3.68) AU17(8.764,-3.68) AU19(7.171,-3.68) AU21(5.577,-3.68) AU35(-5.577,-3.68) AU37(-7.171,-3.68) AU39(-8.764,-3.68) AU41(-10.358,-3.68) AU43(-11.951,-3.68) AU45(-13.545,-3.68) AU47(-15.138,-3.68) AU49(-16.732,-3.68) AU51(-18.325,-3.68) AU53(-19.919,-3.68) AU55(-21.512,-3.68) AV2(20.715,-3.22) AV4(19.122,-3.22) AV6(17.528,-3.22) AV8(15.935,-3.22) AV10(14.341,-3.22) AV12(12.748,-3.22) AV14(11.154,-3.22) AV16(9.561,-3.22) AV18(7.967,-3.22) AV20(6.374,-3.22) AV22(4.78,-3.22) AV34(-4.78,-3.22) AV36(-6.374,-3.22) AV38(-7.967,-3.22) AV40(-9.561,-3.22) AV42(-11.154,-3.22) AV44(-12.748,-3.22) AV46(-14.341,-3.22) AV48(-15.935,-3.22) AV50(-17.528,-3.22) AV52(-19.122,-3.22) AV54(-20.715,-3.22) AW1(21.512,-2.76) AW3(19.919,-2.76) AW5(18.325,-2.76) AW7(16.732,-2.76) AW9(15.138,-2.76) AW11(13.545,-2.76) AW13(11.951,-2.76) AW15(10.358,-2.76) AW17(8.764,-2.76) AW19(7.171,-2.76) AW21(5.577,-2.76) AW35(-5.577,-2.76) AW37(-7.171,-2.76) AW39(-8.764,-2.76) AW41(-10.358,-2.76) AW43(-11.951,-2.76) AW45(-13.545,-2.76) AW47(-15.138,-2.76) AW49(-16.732,-2.76) AW51(-18.325,-2.76) AW53(-19.919,-2.76) AW55(-21.512,-2.76) AY2(20.715,-2.3) AY4(19.122,-2.3) AY6(17.528,-2.3) AY8(15.935,-2.3) AY10(14.341,-2.3) AY12(12.748,-2.3) AY14(11.154,-2.3) AY16(9.561,-2.3) AY18(7.967,-2.3) AY20(6.374,-2.3) AY22(4.78,-2.3) AY34(-4.78,-2.3) AY36(-6.374,-2.3) AY38(-7.967,-2.3) AY40(-9.561,-2.3) AY42(-11.154,-2.3) AY44(-12.748,-2.3) AY46(-14.341,-2.3) AY48(-15.935,-2.3) AY50(-17.528,-2.3) AY52(-19.122,-2.3) AY54(-20.715,-2.3) B6(17.528,-19.78) B8(15.935,-19.78) B10(14.341,-19.78) B12(12.748,-19.78) B14(11.154,-19.78) B16(9.561,-19.78) B18(7.967,-19.78) B20(6.374,-19.78) B22(4.78,-19.78) B24(3.187,-19.78) B26(1.593,-19.78) B28(0,-19.78) B30(-1.593,-19.78) B32(-3.187,-19.78) B34(-4.78,-19.78) B36(-6.374,-19.78) B38(-7.967,-19.78) B40(-9.561,-19.78) B42(-11.154,-19.78) B44(-12.748,-19.78) B46(-14.341,-19.78) B48(-15.935,-19.78) B50(-17.528,-19.78) BA1(21.512,-1.84) BA3(19.919,-1.84) BA5(18.325,-1.84) BA7(16.732,-1.84) BA9(15.138,-1.84) BA11(13.545,-1.84) BA13(11.951,-1.84) BA15(10.358,-1.84) BA17(8.764,-1.84) BA19(7.171,-1.84) BA21(5.577,-1.84) BA35(-5.577,-1.84) BA37(-7.171,-1.84) BA39(-8.764,-1.84) BA41(-10.358,-1.84) BA43(-11.951,-1.84) BA45(-13.545,-1.84) BA47(-15.138,-1.84) BA49(-16.732,-1.84) BA51(-18.325,-1.84) BA53(-19.919,-1.84) BA55(-21.512,-1.84) BB2(20.715,-1.38) BB4(19.122,-1.38) BB6(17.528,-1.38) BB8(15.935,-1.38) BB10(14.341,-1.38) BB12(12.748,-1.38) BB14(11.154,-1.38) BB16(9.561,-1.38) BB18(7.967,-1.38) BB20(6.374,-1.38) BB22(4.78,-1.38) BB34(-4.78,-1.38) BB36(-6.374,-1.38) BB38(-7.967,-1.38) BB40(-9.561,-1.38) BB42(-11.154,-1.38) BB44(-12.748,-1.38) BB46(-14.341,-1.38) BB48(-15.935,-1.38) BB50(-17.528,-1.38) BB52(-19.122,-1.38) BB54(-20.715,-1.38) BC1(21.512,-0.92) BC3(19.919,-0.92) BC5(18.325,-0.92) BC7(16.732,-0.92) BC9(15.138,-0.92) BC11(13.545,-0.92) BC13(11.951,-0.92) BC15(10.358,-0.92) BC17(8.764,-0.92) BC19(7.171,-0.92) BC21(5.577,-0.92) BC35(-5.577,-0.92) BC37(-7.171,-0.92) BC39(-8.764,-0.92) BC41(-10.358,-0.92) BC43(-11.951,-0.92) BC45(-13.545,-0.92) BC47(-15.138,-0.92) BC49(-16.732,-0.92) BC51(-18.325,-0.92) BC53(-19.919,-0.92) BC55(-21.512,-0.92) BD2(20.715,-0.46) BD4(19.122,-0.46) BD6(17.528,-0.46) BD8(15.935,-0.46) BD10(14.341,-0.46) BD12(12.748,-0.46) BD14(11.154,-0.46) BD16(9.561,-0.46) BD18(7.967,-0.46) BD20(6.374,-0.46) BD22(4.78,-0.46) BD34(-4.78,-0.46) BD36(-6.374,-0.46) BD38(-7.967,-0.46) BD40(-9.561,-0.46) BD42(-11.154,-0.46) BD44(-12.748,-0.46) BD46(-14.341,-0.46) BD48(-15.935,-0.46) BD50(-17.528,-0.46) BD52(-19.122,-0.46) BD54(-20.715,-0.46) BE1(21.512,0) BE3(19.919,0) BE5(18.325,0) BE7(16.732,0) BE9(15.138,0) BE11(13.545,0) BE13(11.951,0) BE15(10.358,0) BE17(8.764,0) BE19(7.171,0) BE21(5.577,0) BE35(-5.577,0) BE37(-7.171,0) BE39(-8.764,0) BE41(-10.358,0) BE43(-11.951,0) BE45(-13.545,0) BE47(-15.138,0) BE49(-16.732,0) BE51(-18.325,0) BE53(-19.919,0) BE55(-21.512,0) BF2(20.715,0.46) BF4(19.122,0.46) BF6(17.528,0.46) BF8(15.935,0.46) BF10(14.341,0.46) BF12(12.748,0.46) BF14(11.154,0.46) BF16(9.561,0.46) BF18(7.967,0.46) BF20(6.374,0.46) BF22(4.78,0.46) BF34(-4.78,0.46) BF36(-6.374,0.46) BF38(-7.967,0.46) BF40(-9.561,0.46) BF42(-11.154,0.46) BF44(-12.748,0.46) BF46(-14.341,0.46) BF48(-15.935,0.46) BF50(-17.528,0.46) BF52(-19.122,0.46) BF54(-20.715,0.46) BG1(21.512,0.92) BG3(19.919,0.92) BG5(18.325,0.92) BG7(16.732,0.92) BG9(15.138,0.92) BG11(13.545,0.92) BG13(11.951,0.92) BG15(10.358,0.92) BG17(8.764,0.92) BG19(7.171,0.92) BG21(5.577,0.92) BG35(-5.577,0.92) BG37(-7.171,0.92) BG39(-8.764,0.92) BG41(-10.358,0.92) BG43(-11.951,0.92) BG45(-13.545,0.92) BG47(-15.138,0.92) BG49(-16.732,0.92) BG51(-18.325,0.92) BG53(-19.919,0.92) BG55(-21.512,0.92) BH2(20.715,1.38) BH4(19.122,1.38) BH6(17.528,1.38) BH8(15.935,1.38) BH10(14.341,1.38) BH12(12.748,1.38) BH14(11.154,1.38) BH16(9.561,1.38) BH18(7.967,1.38) BH20(6.374,1.38) BH22(4.78,1.38) BH34(-4.78,1.38) BH36(-6.374,1.38) BH38(-7.967,1.38) BH40(-9.561,1.38) BH42(-11.154,1.38) BH44(-12.748,1.38) BH46(-14.341,1.38) BH48(-15.935,1.38) BH50(-17.528,1.38) BH52(-19.122,1.38) BH54(-20.715,1.38) BJ1(21.512,1.84) BJ3(19.919,1.84) BJ5(18.325,1.84) BJ7(16.732,1.84) BJ9(15.138,1.84) BJ11(13.545,1.84) BJ13(11.951,1.84) BJ15(10.358,1.84) BJ17(8.764,1.84) BJ19(7.171,1.84) BJ21(5.577,1.84) BJ35(-5.577,1.84) BJ37(-7.171,1.84) BJ39(-8.764,1.84) BJ41(-10.358,1.84) BJ43(-11.951,1.84) BJ45(-13.545,1.84) BJ47(-15.138,1.84) BJ49(-16.732,1.84) BJ51(-18.325,1.84) BJ53(-19.919,1.84) BJ55(-21.512,1.84) BK2(20.715,2.3) BK4(19.122,2.3) BK6(17.528,2.3) BK8(15.935,2.3) BK10(14.341,2.3) BK12(12.748,2.3) BK14(11.154,2.3) BK16(9.561,2.3) BK18(7.967,2.3) BK20(6.374,2.3) BK22(4.78,2.3) BK34(-4.78,2.3) BK36(-6.374,2.3) BK38(-7.967,2.3) BK40(-9.561,2.3) BK42(-11.154,2.3) BK44(-12.748,2.3) BK46(-14.341,2.3) BK48(-15.935,2.3) BK50(-17.528,2.3) BK52(-19.122,2.3) BK54(-20.715,2.3) BL1(21.512,2.76) BL3(19.919,2.76) BL5(18.325,2.76) BL7(16.732,2.76) BL9(15.138,2.76) BL11(13.545,2.76) BL13(11.951,2.76) BL15(10.358,2.76) BL17(8.764,2.76) BL19(7.171,2.76) BL21(5.577,2.76) BL35(-5.577,2.76) BL37(-7.171,2.76) BL39(-8.764,2.76) BL41(-10.358,2.76) BL43(-11.951,2.76) BL45(-13.545,2.76) BL47(-15.138,2.76) BL49(-16.732,2.76) BL51(-18.325,2.76) BL53(-19.919,2.76) BL55(-21.512,2.76) BM2(20.715,3.22) BM4(19.122,3.22) BM6(17.528,3.22) BM8(15.935,3.22) BM10(14.341,3.22) BM12(12.748,3.22) BM14(11.154,3.22) BM16(9.561,3.22) BM18(7.967,3.22) BM20(6.374,3.22) BM22(4.78,3.22) BM34(-4.78,3.22) BM36(-6.374,3.22) BM38(-7.967,3.22) BM40(-9.561,3.22) BM42(-11.154,3.22) BM44(-12.748,3.22) BM46(-14.341,3.22) BM48(-15.935,3.22) BM50(-17.528,3.22) BM52(-19.122,3.22) BM54(-20.715,3.22) BN1(21.512,3.68) BN3(19.919,3.68) BN5(18.325,3.68) BN7(16.732,3.68) BN9(15.138,3.68) BN11(13.545,3.68) BN13(11.951,3.68) BN15(10.358,3.68) BN17(8.764,3.68) BN19(7.171,3.68) BN21(5.577,3.68) BN35(-5.577,3.68) BN37(-7.171,3.68) BN39(-8.764,3.68) BN41(-10.358,3.68) BN43(-11.951,3.68) BN45(-13.545,3.68) BN47(-15.138,3.68) BN49(-16.732,3.68) BN51(-18.325,3.68) BN53(-19.919,3.68) BN55(-21.512,3.68) BP2(20.715,4.14) BP4(19.122,4.14) BP6(17.528,4.14) BP8(15.935,4.14) BP10(14.341,4.14) BP12(12.748,4.14) BP14(11.154,4.14) BP16(9.561,4.14) BP18(7.967,4.14) BP20(6.374,4.14) BP22(4.78,4.14) BP34(-4.78,4.14) BP36(-6.374,4.14) BP38(-7.967,4.14) BP40(-9.561,4.14) BP42(-11.154,4.14) BP44(-12.748,4.14) BP46(-14.341,4.14) BP48(-15.935,4.14) BP50(-17.528,4.14) BP52(-19.122,4.14) BP54(-20.715,4.14) BR1(21.512,4.6) BR3(19.919,4.6) BR5(18.325,4.6) BR7(16.732,4.6) BR9(15.138,4.6) BR11(13.545,4.6) BR13(11.951,4.6) BR15(10.358,4.6) BR17(8.764,4.6) BR19(7.171,4.6) BR21(5.577,4.6) BR23(3.984,4.6) BR25(2.39,4.6) BR27(0.797,4.6) BR29(-0.797,4.6) BR31(-2.39,4.6) BR33(-3.984,4.6) BR35(-5.577,4.6) BR37(-7.171,4.6) BR39(-8.764,4.6) BR41(-10.358,4.6) BR43(-11.951,4.6) BR45(-13.545,4.6) BR47(-15.138,4.6) BR49(-16.732,4.6) BR51(-18.325,4.6) BR53(-19.919,4.6) BR55(-21.512,4.6) BT2(20.715,5.06) BT4(19.122,5.06) BT6(17.528,5.06) BT8(15.935,5.06) BT10(14.341,5.06) BT12(12.748,5.06) BT14(11.154,5.06) BT16(9.561,5.06) BT18(7.967,5.06) BT20(6.374,5.06) BT22(4.78,5.06) BT24(3.187,5.06) BT26(1.593,5.06) BT28(0,5.06) BT30(-1.593,5.06) BT32(-3.187,5.06) BT34(-4.78,5.06) BT36(-6.374,5.06) BT38(-7.967,5.06) BT40(-9.561,5.06) BT42(-11.154,5.06) BT44(-12.748,5.06) BT46(-14.341,5.06) BT48(-15.935,5.06) BT50(-17.528,5.06) BT52(-19.122,5.06) BT54(-20.715,5.06) BU1(21.512,5.52) BU3(19.919,5.52) BU5(18.325,5.52) BU7(16.732,5.52) BU9(15.138,5.52) BU11(13.545,5.52) BU13(11.951,5.52) BU15(10.358,5.52) BU17(8.764,5.52) BU19(7.171,5.52) BU21(5.577,5.52) BU23(3.984,5.52) BU25(2.39,5.52) BU27(0.797,5.52) BU29(-0.797,5.52) BU31(-2.39,5.52) BU33(-3.984,5.52) BU35(-5.577,5.52) BU37(-7.171,5.52) BU39(-8.764,5.52) BU41(-10.358,5.52) BU43(-11.951,5.52) BU45(-13.545,5.52) BU47(-15.138,5.52) BU49(-16.732,5.52) BU51(-18.325,5.52) BU53(-19.919,5.52) BU55(-21.512,5.52) BV2(20.715,5.98) BV4(19.122,5.98) BV6(17.528,5.98) BV8(15.935,5.98) BV10(14.341,5.98) BV12(12.748,5.98) BV14(11.154,5.98) BV16(9.561,5.98) BV18(7.967,5.98) BV20(6.374,5.98) BV22(4.78,5.98) BV24(3.187,5.98) BV26(1.593,5.98) BV28(0,5.98) BV30(-1.593,5.98) BV32(-3.187,5.98) BV34(-4.78,5.98) BV36(-6.374,5.98) BV38(-7.967,5.98) BV40(-9.561,5.98) BV42(-11.154,5.98) BV44(-12.748,5.98) BV46(-14.341,5.98) BV48(-15.935,5.98) BV50(-17.528,5.98) BV52(-19.122,5.98) BV54(-20.715,5.98) BW1(21.512,6.44) BW3(19.919,6.44) BW5(18.325,6.44) BW7(16.732,6.44) BW9(15.138,6.44) BW11(13.545,6.44) BW13(11.951,6.44) BW15(10.358,6.44) BW17(8.764,6.44) BW19(7.171,6.44) BW21(5.577,6.44) BW23(3.984,6.44) BW25(2.39,6.44) BW27(0.797,6.44) BW29(-0.797,6.44) BW31(-2.39,6.44) BW33(-3.984,6.44) BW35(-5.577,6.44) BW37(-7.171,6.44) BW39(-8.764,6.44) BW41(-10.358,6.44) BW43(-11.951,6.44) BW45(-13.545,6.44) BW47(-15.138,6.44) BW49(-16.732,6.44) BW51(-18.325,6.44) BW53(-19.919,6.44) BW55(-21.512,6.44) BY2(20.715,6.9) BY4(19.122,6.9) BY6(17.528,6.9) BY8(15.935,6.9) BY10(14.341,6.9) BY12(12.748,6.9) BY14(11.154,6.9) BY16(9.561,6.9) BY18(7.967,6.9) BY20(6.374,6.9) BY22(4.78,6.9) BY24(3.187,6.9) BY26(1.593,6.9) BY28(0,6.9) BY30(-1.593,6.9) BY32(-3.187,6.9) BY34(-4.78,6.9) BY36(-6.374,6.9) BY38(-7.967,6.9) BY40(-9.561,6.9) BY42(-11.154,6.9) BY44(-12.748,6.9) BY46(-14.341,6.9) BY48(-15.935,6.9) BY50(-17.528,6.9) BY52(-19.122,6.9) BY54(-20.715,6.9) C5(18.325,-19.32) C7(16.732,-19.32) C9(15.138,-19.32) C11(13.545,-19.32) C13(11.951,-19.32) C15(10.358,-19.32) C17(8.764,-19.32) C19(7.171,-19.32) C21(5.577,-19.32) C23(3.984,-19.32) C25(2.39,-19.32) C27(0.797,-19.32) C29(-0.797,-19.32) C31(-2.39,-19.32) C33(-3.984,-19.32) C35(-5.577,-19.32) C37(-7.171,-19.32) C39(-8.764,-19.32) C41(-10.358,-19.32) C43(-11.951,-19.32) C45(-13.545,-19.32) C47(-15.138,-19.32) C49(-16.732,-19.32) C51(-18.325,-19.32) CA1(21.512,7.36) CA3(19.919,7.36) CA5(18.325,7.36) CA7(16.732,7.36) CA9(15.138,7.36) CA11(13.545,7.36) CA13(11.951,7.36) CA15(10.358,7.36) CA17(8.764,7.36) CA19(7.171,7.36) CA21(5.577,7.36) CA23(3.984,7.36) CA25(2.39,7.36) CA27(0.797,7.36) CA29(-0.797,7.36) CA31(-2.39,7.36) CA33(-3.984,7.36) CA35(-5.577,7.36) CA37(-7.171,7.36) CA39(-8.764,7.36) CA41(-10.358,7.36) CA43(-11.951,7.36) CA45(-13.545,7.36) CA47(-15.138,7.36) CA49(-16.732,7.36) CA51(-18.325,7.36) CA53(-19.919,7.36) CA55(-21.512,7.36) CB2(20.715,7.82) CB4(19.122,7.82) CB6(17.528,7.82) CB8(15.935,7.82) CB10(14.341,7.82) CB12(12.748,7.82) CB14(11.154,7.82) CB16(9.561,7.82) CB18(7.967,7.82) CB20(6.374,7.82) CB22(4.78,7.82) CB24(3.187,7.82) CB26(1.593,7.82) CB28(0,7.82) CB30(-1.593,7.82) CB32(-3.187,7.82) CB34(-4.78,7.82) CB36(-6.374,7.82) CB38(-7.967,7.82) CB40(-9.561,7.82) CB42(-11.154,7.82) CB44(-12.748,7.82) CB46(-14.341,7.82) CB48(-15.935,7.82) CB50(-17.528,7.82) CB52(-19.122,7.82) CB54(-20.715,7.82) CC1(21.512,8.28) CC3(19.919,8.28) CC5(18.325,8.28) CC7(16.732,8.28) CC9(15.138,8.28) CC11(13.545,8.28) CC13(11.951,8.28) CC15(10.358,8.28) CC17(8.764,8.28) CC19(7.171,8.28) CC21(5.577,8.28) CC23(3.984,8.28) CC25(2.39,8.28) CC27(0.797,8.28) CC29(-0.797,8.28) CC31(-2.39,8.28) CC33(-3.984,8.28) CC35(-5.577,8.28) CC37(-7.171,8.28) CC39(-8.764,8.28) CC41(-10.358,8.28) CC43(-11.951,8.28) CC45(-13.545,8.28) CC47(-15.138,8.28) CC49(-16.732,8.28) CC51(-18.325,8.28) CC53(-19.919,8.28) CC55(-21.512,8.28) CD2(20.715,8.74) CD4(19.122,8.74) CD6(17.528,8.74) CD8(15.935,8.74) CD10(14.341,8.74) CD12(12.748,8.74) CD14(11.154,8.74) CD16(9.561,8.74) CD18(7.967,8.74) CD20(6.374,8.74) CD22(4.78,8.74) CD24(3.187,8.74) CD26(1.593,8.74) CD28(0,8.74) CD30(-1.593,8.74) CD32(-3.187,8.74) CD34(-4.78,8.74) CD36(-6.374,8.74) CD38(-7.967,8.74) CD40(-9.561,8.74) CD42(-11.154,8.74) CD44(-12.748,8.74) CD46(-14.341,8.74) CD48(-15.935,8.74) CD50(-17.528,8.74) CD52(-19.122,8.74) CD54(-20.715,8.74) CE1(21.512,9.2) CE3(19.919,9.2) CE5(18.325,9.2) CE7(16.732,9.2) CE9(15.138,9.2) CE11(13.545,9.2) CE13(11.951,9.2) CE15(10.358,9.2) CE17(8.764,9.2) CE19(7.171,9.2) CE21(5.577,9.2) CE23(3.984,9.2) CE25(2.39,9.2) CE27(0.797,9.2) CE29(-0.797,9.2) CE31(-2.39,9.2) CE33(-3.984,9.2) CE35(-5.577,9.2) CE37(-7.171,9.2) CE39(-8.764,9.2) CE41(-10.358,9.2) CE43(-11.951,9.2) CE45(-13.545,9.2) CE47(-15.138,9.2) CE49(-16.732,9.2) CE51(-18.325,9.2) CE53(-19.919,9.2) CE55(-21.512,9.2) CF2(20.715,9.66) CF4(19.122,9.66) CF6(17.528,9.66) CF8(15.935,9.66) CF10(14.341,9.66) CF12(12.748,9.66) CF14(11.154,9.66) CF16(9.561,9.66) CF18(7.967,9.66) CF20(6.374,9.66) CF22(4.78,9.66) CF24(3.187,9.66) CF26(1.593,9.66) CF28(0,9.66) CF30(-1.593,9.66) CF32(-3.187,9.66) CF34(-4.78,9.66) CF36(-6.374,9.66) CF38(-7.967,9.66) CF40(-9.561,9.66) CF42(-11.154,9.66) CF44(-12.748,9.66) CF46(-14.341,9.66) CF48(-15.935,9.66) CF50(-17.528,9.66) CF52(-19.122,9.66) CF54(-20.715,9.66) CG1(21.512,10.12) CG3(19.919,10.12) CG5(18.325,10.12) CG7(16.732,10.12) CG9(15.138,10.12) CG11(13.545,10.12) CG13(11.951,10.12) CG15(10.358,10.12) CG17(8.764,10.12) CG19(7.171,10.12) CG21(5.577,10.12) CG23(3.984,10.12) CG25(2.39,10.12) CG27(0.797,10.12) CG29(-0.797,10.12) CG31(-2.39,10.12) CG33(-3.984,10.12) CG35(-5.577,10.12) CG37(-7.171,10.12) CG39(-8.764,10.12) CG41(-10.358,10.12) CG43(-11.951,10.12) CG45(-13.545,10.12) CG47(-15.138,10.12) CG49(-16.732,10.12) CG51(-18.325,10.12) CG53(-19.919,10.12) CG55(-21.512,10.12) CH2(20.715,10.58) CH4(19.122,10.58) CH6(17.528,10.58) CH8(15.935,10.58) CH10(14.341,10.58) CH12(12.748,10.58) CH14(11.154,10.58) CH16(9.561,10.58) CH18(7.967,10.58) CH20(6.374,10.58) CH22(4.78,10.58) CH24(3.187,10.58) CH26(1.593,10.58) CH28(0,10.58) CH30(-1.593,10.58) CH32(-3.187,10.58) CH34(-4.78,10.58) CH36(-6.374,10.58) CH38(-7.967,10.58) CH40(-9.561,10.58) CH42(-11.154,10.58) CH44(-12.748,10.58) CH46(-14.341,10.58) CH48(-15.935,10.58) CH50(-17.528,10.58) CH52(-19.122,10.58) CH54(-20.715,10.58) CJ1(21.512,11.04) CJ3(19.919,11.04) CJ5(18.325,11.04) CJ7(16.732,11.04) CJ9(15.138,11.04) CJ11(13.545,11.04) CJ13(11.951,11.04) CJ15(10.358,11.04) CJ17(8.764,11.04) CJ19(7.171,11.04) CJ21(5.577,11.04) CJ23(3.984,11.04) CJ25(2.39,11.04) CJ27(0.797,11.04) CJ29(-0.797,11.04) CJ31(-2.39,11.04) CJ33(-3.984,11.04) CJ35(-5.577,11.04) CJ37(-7.171,11.04) CJ39(-8.764,11.04) CJ41(-10.358,11.04) CJ43(-11.951,11.04) CJ45(-13.545,11.04) CJ47(-15.138,11.04) CJ49(-16.732,11.04) CJ51(-18.325,11.04) CJ53(-19.919,11.04) CJ55(-21.512,11.04) CK2(20.715,11.5) CK4(19.122,11.5) CK6(17.528,11.5) CK8(15.935,11.5) CK10(14.341,11.5) CK12(12.748,11.5) CK14(11.154,11.5) CK16(9.561,11.5) CK18(7.967,11.5) CK20(6.374,11.5) CK22(4.78,11.5) CK24(3.187,11.5) CK26(1.593,11.5) CK28(0,11.5) CK30(-1.593,11.5) CK32(-3.187,11.5) CK34(-4.78,11.5) CK36(-6.374,11.5) CK38(-7.967,11.5) CK40(-9.561,11.5) CK42(-11.154,11.5) CK44(-12.748,11.5) CK46(-14.341,11.5) CK48(-15.935,11.5) CK50(-17.528,11.5) CK52(-19.122,11.5) CK54(-20.715,11.5) CL1(21.512,11.96) CL3(19.919,11.96) CL5(18.325,11.96) CL7(16.732,11.96) CL9(15.138,11.96) CL11(13.545,11.96) CL13(11.951,11.96) CL15(10.358,11.96) CL17(8.764,11.96) CL19(7.171,11.96) CL21(5.577,11.96) CL23(3.984,11.96) CL25(2.39,11.96) CL27(0.797,11.96) CL29(-0.797,11.96) CL31(-2.39,11.96) CL33(-3.984,11.96) CL35(-5.577,11.96) CL37(-7.171,11.96) CL39(-8.764,11.96) CL41(-10.358,11.96) CL43(-11.951,11.96) CL45(-13.545,11.96) CL47(-15.138,11.96) CL49(-16.732,11.96) CL51(-18.325,11.96) CL53(-19.919,11.96) CL55(-21.512,11.96) CM2(20.715,12.42) CM4(19.122,12.42) CM6(17.528,12.42) CM8(15.935,12.42) CM10(14.341,12.42) CM12(12.748,12.42) CM14(11.154,12.42) CM16(9.561,12.42) CM18(7.967,12.42) CM20(6.374,12.42) CM22(4.78,12.42) CM24(3.187,12.42) CM26(1.593,12.42) CM28(0,12.42) CM30(-1.593,12.42) CM32(-3.187,12.42) CM34(-4.78,12.42) CM36(-6.374,12.42) CM38(-7.967,12.42) CM40(-9.561,12.42) CM42(-11.154,12.42) CM44(-12.748,12.42) CM46(-14.341,12.42) CM48(-15.935,12.42) CM50(-17.528,12.42) CM52(-19.122,12.42) CM54(-20.715,12.42) CN1(21.512,12.88) CN3(19.919,12.88) CN5(18.325,12.88) CN7(16.732,12.88) CN9(15.138,12.88) CN11(13.545,12.88) CN13(11.951,12.88) CN15(10.358,12.88) CN17(8.764,12.88) CN19(7.171,12.88) CN21(5.577,12.88) CN23(3.984,12.88) CN25(2.39,12.88) CN27(0.797,12.88) CN29(-0.797,12.88) CN31(-2.39,12.88) CN33(-3.984,12.88) CN35(-5.577,12.88) CN37(-7.171,12.88) CN39(-8.764,12.88) CN41(-10.358,12.88) CN43(-11.951,12.88) CN45(-13.545,12.88) CN47(-15.138,12.88) CN49(-16.732,12.88) CN51(-18.325,12.88) CN53(-19.919,12.88) CN55(-21.512,12.88) CP2(20.715,13.34) CP4(19.122,13.34) CP6(17.528,13.34) CP8(15.935,13.34) CP10(14.341,13.34) CP12(12.748,13.34) CP14(11.154,13.34) CP16(9.561,13.34) CP18(7.967,13.34) CP20(6.374,13.34) CP22(4.78,13.34) CP24(3.187,13.34) CP26(1.593,13.34) CP28(0,13.34) CP30(-1.593,13.34) CP32(-3.187,13.34) CP34(-4.78,13.34) CP36(-6.374,13.34) CP38(-7.967,13.34) CP40(-9.561,13.34) CP42(-11.154,13.34) CP44(-12.748,13.34) CP46(-14.341,13.34) CP48(-15.935,13.34) CP50(-17.528,13.34) CP52(-19.122,13.34) CP54(-20.715,13.34) CR1(21.512,13.8) CR3(19.919,13.8) CR5(18.325,13.8) CR7(16.732,13.8) CR9(15.138,13.8) CR11(13.545,13.8) CR13(11.951,13.8) CR15(10.358,13.8) CR17(8.764,13.8) CR19(7.171,13.8) CR21(5.577,13.8) CR23(3.984,13.8) CR25(2.39,13.8) CR27(0.797,13.8) CR29(-0.797,13.8) CR31(-2.39,13.8) CR33(-3.984,13.8) CR35(-5.577,13.8) CR37(-7.171,13.8) CR39(-8.764,13.8) CR41(-10.358,13.8) CR43(-11.951,13.8) CR45(-13.545,13.8) CR47(-15.138,13.8) CR49(-16.732,13.8) CR51(-18.325,13.8) CR53(-19.919,13.8) CR55(-21.512,13.8) CT2(20.715,14.26) CT4(19.122,14.26) CT6(17.528,14.26) CT8(15.935,14.26) CT10(14.341,14.26) CT12(12.748,14.26) CT14(11.154,14.26) CT16(9.561,14.26) CT18(7.967,14.26) CT20(6.374,14.26) CT22(4.78,14.26) CT24(3.187,14.26) CT26(1.593,14.26) CT28(0,14.26) CT30(-1.593,14.26) CT32(-3.187,14.26) CT34(-4.78,14.26) CT36(-6.374,14.26) CT38(-7.967,14.26) CT40(-9.561,14.26) CT42(-11.154,14.26) CT44(-12.748,14.26) CT46(-14.341,14.26) CT48(-15.935,14.26) CT50(-17.528,14.26) CT52(-19.122,14.26) CT54(-20.715,14.26) CU1(21.512,14.72) CU3(19.919,14.72) CU5(18.325,14.72) CU7(16.732,14.72) CU9(15.138,14.72) CU11(13.545,14.72) CU13(11.951,14.72) CU15(10.358,14.72) CU17(8.764,14.72) CU19(7.171,14.72) CU21(5.577,14.72) CU23(3.984,14.72) CU25(2.39,14.72) CU27(0.797,14.72) CU29(-0.797,14.72) CU31(-2.39,14.72) CU33(-3.984,14.72) CU35(-5.577,14.72) CU37(-7.171,14.72) CU39(-8.764,14.72) CU41(-10.358,14.72) CU43(-11.951,14.72) CU45(-13.545,14.72) CU47(-15.138,14.72) CU49(-16.732,14.72) CU51(-18.325,14.72) CU53(-19.919,14.72) CU55(-21.512,14.72) CV2(20.715,15.18) CV4(19.122,15.18) CV6(17.528,15.18) CV8(15.935,15.18) CV10(14.341,15.18) CV12(12.748,15.18) CV14(11.154,15.18) CV16(9.561,15.18) CV18(7.967,15.18) CV20(6.374,15.18) CV22(4.78,15.18) CV24(3.187,15.18) CV26(1.593,15.18) CV28(0,15.18) CV30(-1.593,15.18) CV32(-3.187,15.18) CV34(-4.78,15.18) CV36(-6.374,15.18) CV38(-7.967,15.18) CV40(-9.561,15.18) CV42(-11.154,15.18) CV44(-12.748,15.18) CV46(-14.341,15.18) CV48(-15.935,15.18) CV50(-17.528,15.18) CV52(-19.122,15.18) CV54(-20.715,15.18) CW1(21.512,15.64) CW3(19.919,15.64) CW5(18.325,15.64) CW7(16.732,15.64) CW9(15.138,15.64) CW11(13.545,15.64) CW13(11.951,15.64) CW15(10.358,15.64) CW17(8.764,15.64) CW19(7.171,15.64) CW21(5.577,15.64) CW23(3.984,15.64) CW25(2.39,15.64) CW27(0.797,15.64) CW29(-0.797,15.64) CW31(-2.39,15.64) CW33(-3.984,15.64) CW35(-5.577,15.64) CW37(-7.171,15.64) CW39(-8.764,15.64) CW41(-10.358,15.64) CW43(-11.951,15.64) CW45(-13.545,15.64) CW47(-15.138,15.64) CW49(-16.732,15.64) CW51(-18.325,15.64) CW53(-19.919,15.64) CW55(-21.512,15.64) CY2(20.715,16.1) CY4(19.122,16.1) CY6(17.528,16.1) CY8(15.935,16.1) CY10(14.341,16.1) CY12(12.748,16.1) CY14(11.154,16.1) CY16(9.561,16.1) CY18(7.967,16.1) CY20(6.374,16.1) CY22(4.78,16.1) CY24(3.187,16.1) CY26(1.593,16.1) CY28(0,16.1) CY30(-1.593,16.1) CY32(-3.187,16.1) CY34(-4.78,16.1) CY36(-6.374,16.1) CY38(-7.967,16.1) CY40(-9.561,16.1) CY42(-11.154,16.1) CY44(-12.748,16.1) CY46(-14.341,16.1) CY48(-15.935,16.1) CY50(-17.528,16.1) CY52(-19.122,16.1) CY54(-20.715,16.1) D4(19.122,-18.86) D6(17.528,-18.86) D8(15.935,-18.86) D10(14.341,-18.86) D12(12.748,-18.86) D14(11.154,-18.86) D16(9.561,-18.86) D18(7.967,-18.86) D20(6.374,-18.86) D22(4.78,-18.86) D24(3.187,-18.86) D26(1.593,-18.86) D28(0,-18.86) D30(-1.593,-18.86) D32(-3.187,-18.86) D34(-4.78,-18.86) D36(-6.374,-18.86) D38(-7.967,-18.86) D40(-9.561,-18.86) D42(-11.154,-18.86) D44(-12.748,-18.86) D46(-14.341,-18.86) D48(-15.935,-18.86) D50(-17.528,-18.86) D52(-19.122,-18.86) DA1(21.512,16.56) DA3(19.919,16.56) DA5(18.325,16.56) DA7(16.732,16.56) DA9(15.138,16.56) DA11(13.545,16.56) DA13(11.951,16.56) DA15(10.358,16.56) DA17(8.764,16.56) DA19(7.171,16.56) DA21(5.577,16.56) DA23(3.984,16.56) DA25(2.39,16.56) DA27(0.797,16.56) DA29(-0.797,16.56) DA31(-2.39,16.56) DA33(-3.984,16.56) DA35(-5.577,16.56) DA37(-7.171,16.56) DA39(-8.764,16.56) DA41(-10.358,16.56) DA43(-11.951,16.56) DA45(-13.545,16.56) DA47(-15.138,16.56) DA49(-16.732,16.56) DA51(-18.325,16.56) DA53(-19.919,16.56) DA55(-21.512,16.56) DB2(20.715,17.02) DB4(19.122,17.02) DB6(17.528,17.02) DB8(15.935,17.02) DB10(14.341,17.02) DB12(12.748,17.02) DB14(11.154,17.02) DB16(9.561,17.02) DB18(7.967,17.02) DB20(6.374,17.02) DB22(4.78,17.02) DB24(3.187,17.02) DB26(1.593,17.02) DB28(0,17.02) DB30(-1.593,17.02) DB32(-3.187,17.02) DB34(-4.78,17.02) DB36(-6.374,17.02) DB38(-7.967,17.02) DB40(-9.561,17.02) DB42(-11.154,17.02) DB44(-12.748,17.02) DB46(-14.341,17.02) DB48(-15.935,17.02) DB50(-17.528,17.02) DB52(-19.122,17.02) DB54(-20.715,17.02) DC1(21.512,17.48) DC3(19.919,17.48) DC5(18.325,17.48) DC7(16.732,17.48) DC9(15.138,17.48) DC11(13.545,17.48) DC13(11.951,17.48) DC15(10.358,17.48) DC17(8.764,17.48) DC19(7.171,17.48) DC21(5.577,17.48) DC23(3.984,17.48) DC25(2.39,17.48) DC27(0.797,17.48) DC29(-0.797,17.48) DC31(-2.39,17.48) DC33(-3.984,17.48) DC35(-5.577,17.48) DC37(-7.171,17.48) DC39(-8.764,17.48) DC41(-10.358,17.48) DC43(-11.951,17.48) DC45(-13.545,17.48) DC47(-15.138,17.48) DC49(-16.732,17.48) DC51(-18.325,17.48) DC53(-19.919,17.48) DC55(-21.512,17.48) DD2(20.715,17.94) DD4(19.122,17.94) DD6(17.528,17.94) DD8(15.935,17.94) DD10(14.341,17.94) DD12(12.748,17.94) DD14(11.154,17.94) DD16(9.561,17.94) DD18(7.967,17.94) DD20(6.374,17.94) DD22(4.78,17.94) DD24(3.187,17.94) DD26(1.593,17.94) DD28(0,17.94) DD30(-1.593,17.94) DD32(-3.187,17.94) DD34(-4.78,17.94) DD36(-6.374,17.94) DD38(-7.967,17.94) DD40(-9.561,17.94) DD42(-11.154,17.94) DD44(-12.748,17.94) DD46(-14.341,17.94) DD48(-15.935,17.94) DD50(-17.528,17.94) DD52(-19.122,17.94) DD54(-20.715,17.94) DE3(19.919,18.4) DE5(18.325,18.4) DE7(16.732,18.4) DE9(15.138,18.4) DE11(13.545,18.4) DE13(11.951,18.4) DE15(10.358,18.4) DE17(8.764,18.4) DE19(7.171,18.4) DE21(5.577,18.4) DE23(3.984,18.4) DE25(2.39,18.4) DE27(0.797,18.4) DE29(-0.797,18.4) DE31(-2.39,18.4) DE33(-3.984,18.4) DE35(-5.577,18.4) DE37(-7.171,18.4) DE39(-8.764,18.4) DE41(-10.358,18.4) DE43(-11.951,18.4) DE45(-13.545,18.4) DE47(-15.138,18.4) DE49(-16.732,18.4) DE51(-18.325,18.4) DE53(-19.919,18.4) DF4(19.122,18.86) DF6(17.528,18.86) DF8(15.935,18.86) DF10(14.341,18.86) DF12(12.748,18.86) DF14(11.154,18.86) DF16(9.561,18.86) DF18(7.967,18.86) DF20(6.374,18.86) DF22(4.78,18.86) DF24(3.187,18.86) DF26(1.593,18.86) DF28(0,18.86) DF30(-1.593,18.86) DF32(-3.187,18.86) DF34(-4.78,18.86) DF36(-6.374,18.86) DF38(-7.967,18.86) DF40(-9.561,18.86) DF42(-11.154,18.86) DF44(-12.748,18.86) DF46(-14.341,18.86) DF48(-15.935,18.86) DF50(-17.528,18.86) DF52(-19.122,18.86) DG5(18.325,19.32) DG7(16.732,19.32) DG9(15.138,19.32) DG11(13.545,19.32) DG13(11.951,19.32) DG15(10.358,19.32) DG17(8.764,19.32) DG19(7.171,19.32) DG21(5.577,19.32) DG23(3.984,19.32) DG25(2.39,19.32) DG27(0.797,19.32) DG29(-0.797,19.32) DG31(-2.39,19.32) DG33(-3.984,19.32) DG35(-5.577,19.32) DG37(-7.171,19.32) DG39(-8.764,19.32) DG41(-10.358,19.32) DG43(-11.951,19.32) DG45(-13.545,19.32) DG47(-15.138,19.32) DG49(-16.732,19.32) DG51(-18.325,19.32) DH6(17.528,19.78) DH8(15.935,19.78) DH10(14.341,19.78) DH12(12.748,19.78) DH14(11.154,19.78) DH16(9.561,19.78) DH18(7.967,19.78) DH20(6.374,19.78) DH22(4.78,19.78) DH24(3.187,19.78) DH26(1.593,19.78) DH28(0,19.78) DH30(-1.593,19.78) DH32(-3.187,19.78) DH34(-4.78,19.78) DH36(-6.374,19.78) DH38(-7.967,19.78) DH40(-9.561,19.78) DH42(-11.154,19.78) DH44(-12.748,19.78) DH46(-14.341,19.78) DH48(-15.935,19.78) DH50(-17.528,19.78) DJ7(16.732,20.24) DJ9(15.138,20.24) DJ11(13.545,20.24) DJ13(11.951,20.24) DJ15(10.358,20.24) DJ17(8.764,20.24) DJ19(7.171,20.24) DJ21(5.577,20.24) DJ23(3.984,20.24) DJ25(2.39,20.24) DJ27(0.797,20.24) DJ29(-0.797,20.24) DJ31(-2.39,20.24) DJ33(-3.984,20.24) DJ35(-5.577,20.24) DJ37(-7.171,20.24) DJ39(-8.764,20.24) DJ41(-10.358,20.24) DJ43(-11.951,20.24) DJ45(-13.545,20.24) DJ47(-15.138,20.24) DJ49(-16.732,20.24) E3(19.919,-18.4) E5(18.325,-18.4) E7(16.732,-18.4) E9(15.138,-18.4) E11(13.545,-18.4) E13(11.951,-18.4) E15(10.358,-18.4) E17(8.764,-18.4) E19(7.171,-18.4) E21(5.577,-18.4) E23(3.984,-18.4) E25(2.39,-18.4) E27(0.797,-18.4) E29(-0.797,-18.4) E31(-2.39,-18.4) E33(-3.984,-18.4) E35(-5.577,-18.4) E37(-7.171,-18.4) E39(-8.764,-18.4) E41(-10.358,-18.4) E43(-11.951,-18.4) E45(-13.545,-18.4) E47(-15.138,-18.4) E49(-16.732,-18.4) E51(-18.325,-18.4) E53(-19.919,-18.4) F2(20.715,-17.94) F4(19.122,-17.94) F6(17.528,-17.94) F8(15.935,-17.94) F10(14.341,-17.94) F12(12.748,-17.94) F14(11.154,-17.94) F16(9.561,-17.94) F18(7.967,-17.94) F20(6.374,-17.94) F22(4.78,-17.94) F24(3.187,-17.94) F26(1.593,-17.94) F28(0,-17.94) F30(-1.593,-17.94) F32(-3.187,-17.94) F34(-4.78,-17.94) F36(-6.374,-17.94) F38(-7.967,-17.94) F40(-9.561,-17.94) F42(-11.154,-17.94) F44(-12.748,-17.94) F46(-14.341,-17.94) F48(-15.935,-17.94) F50(-17.528,-17.94) F52(-19.122,-17.94) F54(-20.715,-17.94) G1(21.512,-17.48) G3(19.919,-17.48) G5(18.325,-17.48) G7(16.732,-17.48) G9(15.138,-17.48) G11(13.545,-17.48) G13(11.951,-17.48) G15(10.358,-17.48) G17(8.764,-17.48) G19(7.171,-17.48) G21(5.577,-17.48) G23(3.984,-17.48) G25(2.39,-17.48) G27(0.797,-17.48) G29(-0.797,-17.48) G31(-2.39,-17.48) G33(-3.984,-17.48) G35(-5.577,-17.48) G37(-7.171,-17.48) G39(-8.764,-17.48) G41(-10.358,-17.48) G43(-11.951,-17.48) G45(-13.545,-17.48) G47(-15.138,-17.48) G49(-16.732,-17.48) G51(-18.325,-17.48) G53(-19.919,-17.48) G55(-21.512,-17.48) H2(20.715,-17.02) H4(19.122,-17.02) H6(17.528,-17.02) H8(15.935,-17.02) H10(14.341,-17.02) H12(12.748,-17.02) H14(11.154,-17.02) H16(9.561,-17.02) H18(7.967,-17.02) H20(6.374,-17.02) H22(4.78,-17.02) H24(3.187,-17.02) H26(1.593,-17.02) H28(0,-17.02) H30(-1.593,-17.02) H32(-3.187,-17.02) H34(-4.78,-17.02) H36(-6.374,-17.02) H38(-7.967,-17.02) H40(-9.561,-17.02) H42(-11.154,-17.02) H44(-12.748,-17.02) H46(-14.341,-17.02) H48(-15.935,-17.02) H50(-17.528,-17.02) H52(-19.122,-17.02) H54(-20.715,-17.02) J1(21.512,-16.56) J3(19.919,-16.56) J5(18.325,-16.56) J7(16.732,-16.56) J9(15.138,-16.56) J11(13.545,-16.56) J13(11.951,-16.56) J15(10.358,-16.56) J17(8.764,-16.56) J19(7.171,-16.56) J21(5.577,-16.56) J23(3.984,-16.56) J25(2.39,-16.56) J27(0.797,-16.56) J29(-0.797,-16.56) J31(-2.39,-16.56) J33(-3.984,-16.56) J35(-5.577,-16.56) J37(-7.171,-16.56) J39(-8.764,-16.56) J41(-10.358,-16.56) J43(-11.951,-16.56) J45(-13.545,-16.56) J47(-15.138,-16.56) J49(-16.732,-16.56) J51(-18.325,-16.56) J53(-19.919,-16.56) J55(-21.512,-16.56) K2(20.715,-16.1) K4(19.122,-16.1) K6(17.528,-16.1) K8(15.935,-16.1) K10(14.341,-16.1) K12(12.748,-16.1) K14(11.154,-16.1) K16(9.561,-16.1) K18(7.967,-16.1) K20(6.374,-16.1) K22(4.78,-16.1) K24(3.187,-16.1) K26(1.593,-16.1) K28(0,-16.1) K30(-1.593,-16.1) K32(-3.187,-16.1) K34(-4.78,-16.1) K36(-6.374,-16.1) K38(-7.967,-16.1) K40(-9.561,-16.1) K42(-11.154,-16.1) K44(-12.748,-16.1) K46(-14.341,-16.1) K48(-15.935,-16.1) K50(-17.528,-16.1) K52(-19.122,-16.1) K54(-20.715,-16.1) L1(21.512,-15.64) L3(19.919,-15.64) L5(18.325,-15.64) L7(16.732,-15.64) L9(15.138,-15.64) L11(13.545,-15.64) L13(11.951,-15.64) L15(10.358,-15.64) L17(8.764,-15.64) L19(7.171,-15.64) L21(5.577,-15.64) L23(3.984,-15.64) L25(2.39,-15.64) L27(0.797,-15.64) L29(-0.797,-15.64) L31(-2.39,-15.64) L33(-3.984,-15.64) L35(-5.577,-15.64) L37(-7.171,-15.64) L39(-8.764,-15.64) L41(-10.358,-15.64) L43(-11.951,-15.64) L45(-13.545,-15.64) L47(-15.138,-15.64) L49(-16.732,-15.64) L51(-18.325,-15.64) L53(-19.919,-15.64) L55(-21.512,-15.64) M2(20.715,-15.18) M4(19.122,-15.18) M6(17.528,-15.18) M8(15.935,-15.18) M10(14.341,-15.18) M12(12.748,-15.18) M14(11.154,-15.18) M16(9.561,-15.18) M18(7.967,-15.18) M20(6.374,-15.18) M22(4.78,-15.18) M24(3.187,-15.18) M26(1.593,-15.18) M28(0,-15.18) M30(-1.593,-15.18) M32(-3.187,-15.18) M34(-4.78,-15.18) M36(-6.374,-15.18) M38(-7.967,-15.18) M40(-9.561,-15.18) M42(-11.154,-15.18) M44(-12.748,-15.18) M46(-14.341,-15.18) M48(-15.935,-15.18) M50(-17.528,-15.18) M52(-19.122,-15.18) M54(-20.715,-15.18) N1(21.512,-14.72) N3(19.919,-14.72) N5(18.325,-14.72) N7(16.732,-14.72) N9(15.138,-14.72) N11(13.545,-14.72) N13(11.951,-14.72) N15(10.358,-14.72) N17(8.764,-14.72) N19(7.171,-14.72) N21(5.577,-14.72) N23(3.984,-14.72) N25(2.39,-14.72) N27(0.797,-14.72) N29(-0.797,-14.72) N31(-2.39,-14.72) N33(-3.984,-14.72) N35(-5.577,-14.72) N37(-7.171,-14.72) N39(-8.764,-14.72) N41(-10.358,-14.72) N43(-11.951,-14.72) N45(-13.545,-14.72) N47(-15.138,-14.72) N49(-16.732,-14.72) N51(-18.325,-14.72) N53(-19.919,-14.72) N55(-21.512,-14.72) P2(20.715,-14.26) P4(19.122,-14.26) P6(17.528,-14.26) P8(15.935,-14.26) P10(14.341,-14.26) P12(12.748,-14.26) P14(11.154,-14.26) P16(9.561,-14.26) P18(7.967,-14.26) P20(6.374,-14.26) P22(4.78,-14.26) P24(3.187,-14.26) P26(1.593,-14.26) P28(0,-14.26) P30(-1.593,-14.26) P32(-3.187,-14.26) P34(-4.78,-14.26) P36(-6.374,-14.26) P38(-7.967,-14.26) P40(-9.561,-14.26) P42(-11.154,-14.26) P44(-12.748,-14.26) P46(-14.341,-14.26) P48(-15.935,-14.26) P50(-17.528,-14.26) P52(-19.122,-14.26) P54(-20.715,-14.26) R1(21.512,-13.8) R3(19.919,-13.8) R5(18.325,-13.8) R7(16.732,-13.8) R9(15.138,-13.8) R11(13.545,-13.8) R13(11.951,-13.8) R15(10.358,-13.8) R17(8.764,-13.8) R19(7.171,-13.8) R21(5.577,-13.8) R23(3.984,-13.8) R25(2.39,-13.8) R27(0.797,-13.8) R29(-0.797,-13.8) R31(-2.39,-13.8) R33(-3.984,-13.8) R35(-5.577,-13.8) R37(-7.171,-13.8) R39(-8.764,-13.8) R41(-10.358,-13.8) R43(-11.951,-13.8) R45(-13.545,-13.8) R47(-15.138,-13.8) R49(-16.732,-13.8) R51(-18.325,-13.8) R53(-19.919,-13.8) R55(-21.512,-13.8) T2(20.715,-13.34) T4(19.122,-13.34) T6(17.528,-13.34) T8(15.935,-13.34) T10(14.341,-13.34) T12(12.748,-13.34) T14(11.154,-13.34) T16(9.561,-13.34) T18(7.967,-13.34) T20(6.374,-13.34) T22(4.78,-13.34) T24(3.187,-13.34) T26(1.593,-13.34) T28(0,-13.34) T30(-1.593,-13.34) T32(-3.187,-13.34) T34(-4.78,-13.34) T36(-6.374,-13.34) T38(-7.967,-13.34) T40(-9.561,-13.34) T42(-11.154,-13.34) T44(-12.748,-13.34) T46(-14.341,-13.34) T48(-15.935,-13.34) T50(-17.528,-13.34) T52(-19.122,-13.34) T54(-20.715,-13.34) U1(21.512,-12.88) U3(19.919,-12.88) U5(18.325,-12.88) U7(16.732,-12.88) U9(15.138,-12.88) U11(13.545,-12.88) U13(11.951,-12.88) U15(10.358,-12.88) U17(8.764,-12.88) U19(7.171,-12.88) U21(5.577,-12.88) U23(3.984,-12.88) U25(2.39,-12.88) U27(0.797,-12.88) U29(-0.797,-12.88) U31(-2.39,-12.88) U33(-3.984,-12.88) U35(-5.577,-12.88) U37(-7.171,-12.88) U39(-8.764,-12.88) U41(-10.358,-12.88) U43(-11.951,-12.88) U45(-13.545,-12.88) U47(-15.138,-12.88) U49(-16.732,-12.88) U51(-18.325,-12.88) U53(-19.919,-12.88) U55(-21.512,-12.88) V2(20.715,-12.42) V4(19.122,-12.42) V6(17.528,-12.42) V8(15.935,-12.42) V10(14.341,-12.42) V12(12.748,-12.42) V14(11.154,-12.42) V16(9.561,-12.42) V18(7.967,-12.42) V20(6.374,-12.42) V22(4.78,-12.42) V24(3.187,-12.42) V26(1.593,-12.42) V28(0,-12.42) V30(-1.593,-12.42) V32(-3.187,-12.42) V34(-4.78,-12.42) V36(-6.374,-12.42) V38(-7.967,-12.42) V40(-9.561,-12.42) V42(-11.154,-12.42) V44(-12.748,-12.42) V46(-14.341,-12.42) V48(-15.935,-12.42) V50(-17.528,-12.42) V52(-19.122,-12.42) V54(-20.715,-12.42) W1(21.512,-11.96) W3(19.919,-11.96) W5(18.325,-11.96) W7(16.732,-11.96) W9(15.138,-11.96) W11(13.545,-11.96) W13(11.951,-11.96) W15(10.358,-11.96) W17(8.764,-11.96) W19(7.171,-11.96) W21(5.577,-11.96) W23(3.984,-11.96) W25(2.39,-11.96) W27(0.797,-11.96) W29(-0.797,-11.96) W31(-2.39,-11.96) W33(-3.984,-11.96) W35(-5.577,-11.96) W37(-7.171,-11.96) W39(-8.764,-11.96) W41(-10.358,-11.96) W43(-11.951,-11.96) W45(-13.545,-11.96) W47(-15.138,-11.96) W49(-16.732,-11.96) W51(-18.325,-11.96) W53(-19.919,-11.96) W55(-21.512,-11.96) Y2(20.715,-11.5) Y4(19.122,-11.5) Y6(17.528,-11.5) Y8(15.935,-11.5) Y10(14.341,-11.5) Y12(12.748,-11.5) Y14(11.154,-11.5) Y16(9.561,-11.5) Y18(7.967,-11.5) Y20(6.374,-11.5) Y22(4.78,-11.5) Y24(3.187,-11.5) Y26(1.593,-11.5) Y28(0,-11.5) Y30(-1.593,-11.5) Y32(-3.187,-11.5) Y34(-4.78,-11.5) Y36(-6.374,-11.5) Y38(-7.967,-11.5) Y40(-9.561,-11.5) Y42(-11.154,-11.5) Y44(-12.748,-11.5) Y46(-14.341,-11.5) Y48(-15.935,-11.5) Y50(-17.528,-11.5) Y52(-19.122,-11.5) Y54(-20.715,-11.5)
